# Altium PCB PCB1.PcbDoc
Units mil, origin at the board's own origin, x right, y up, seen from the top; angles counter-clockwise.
Board outline 2600 x 2600 mil, 4 copper layers (Top Layer, Layer 1, Layer 2, Bottom Layer), stack 68.756 mil thick; 22 components, 108 nets, 300 pads, 190 vias.
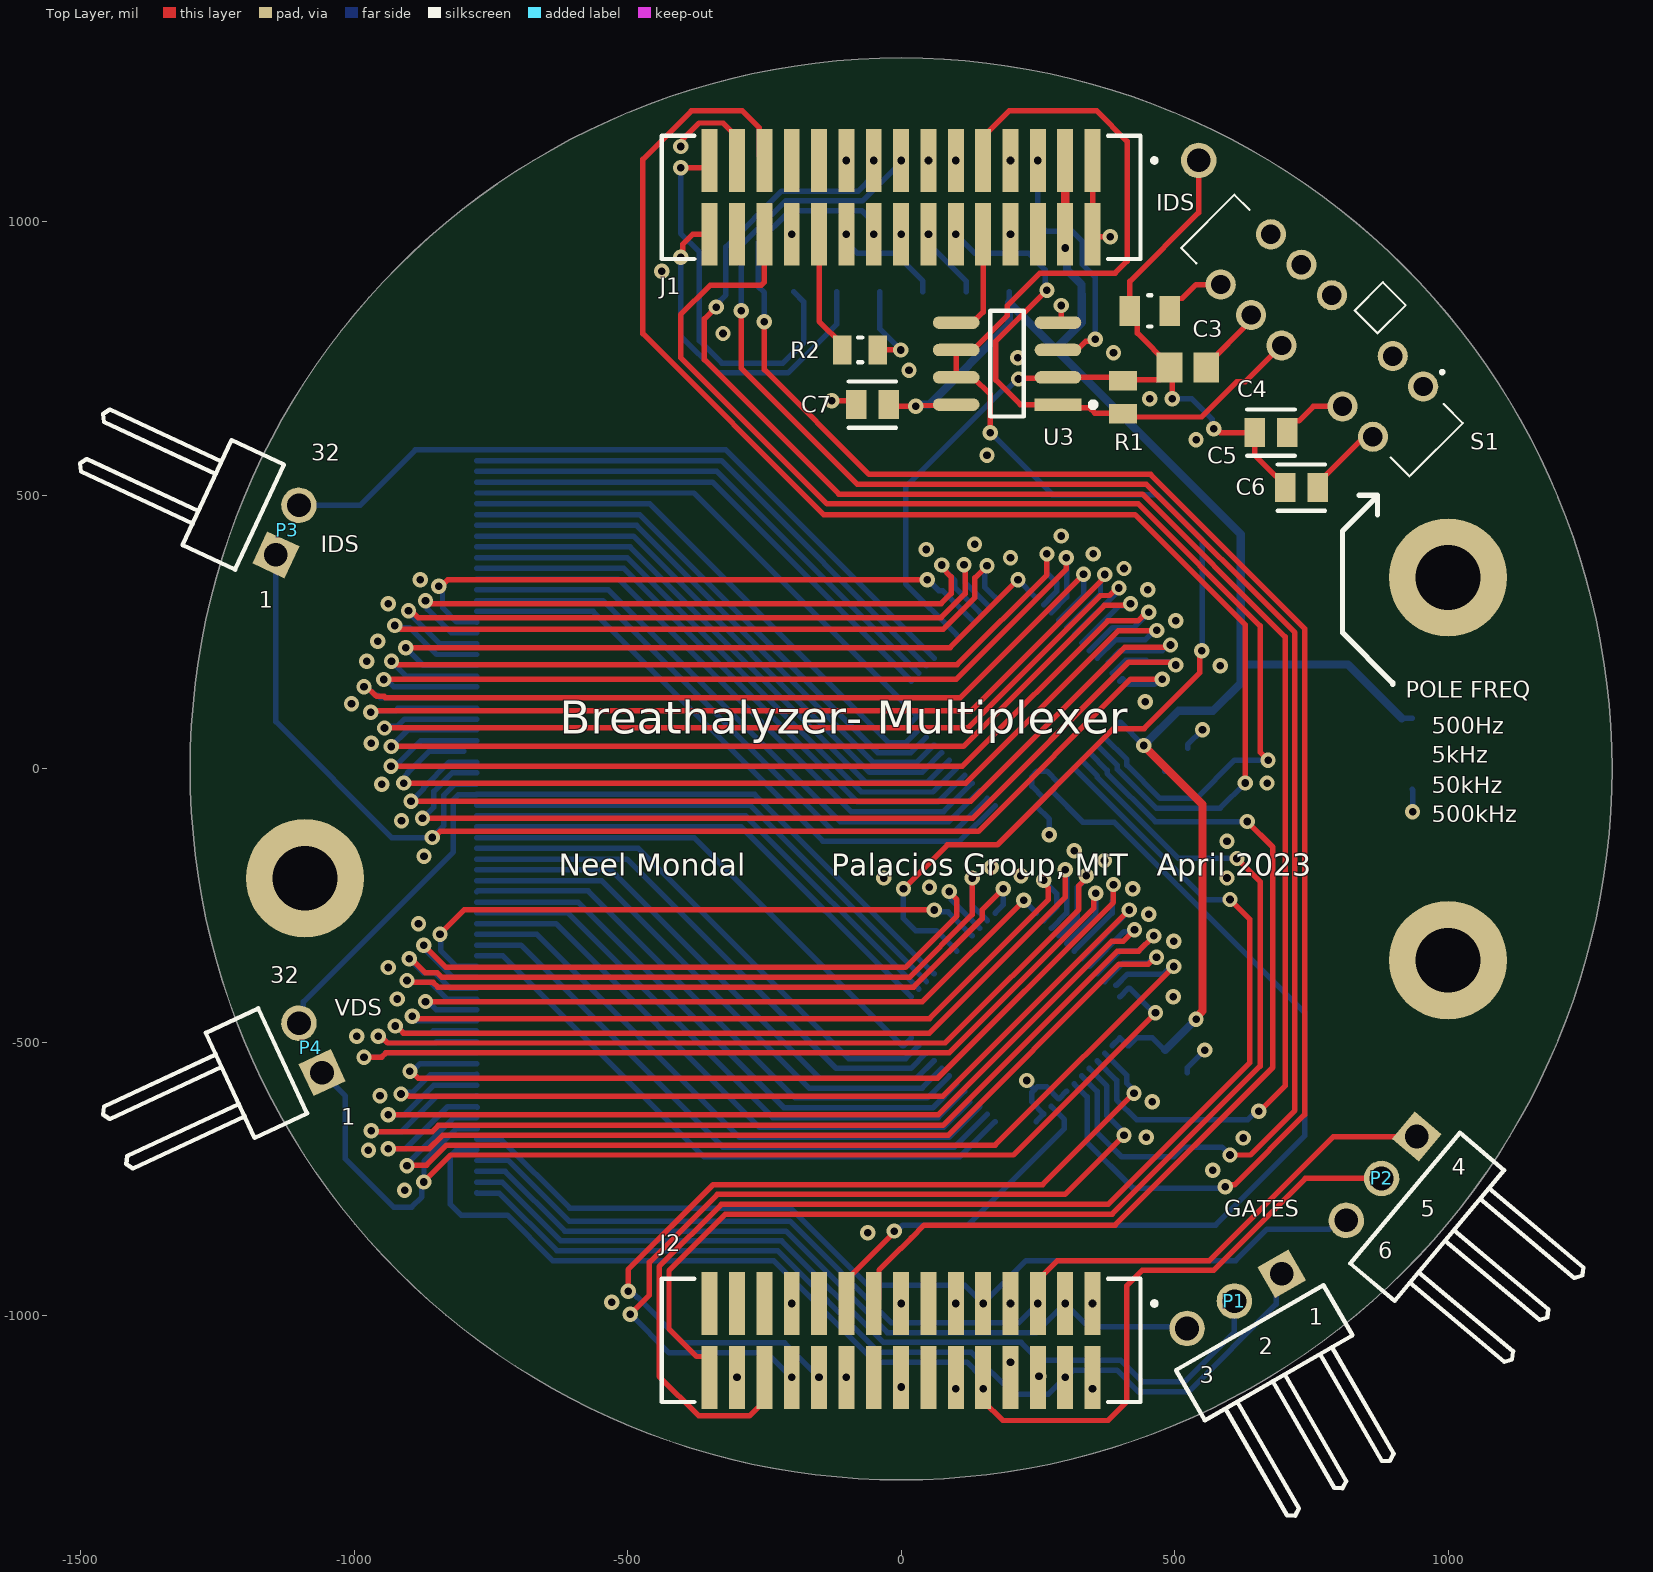
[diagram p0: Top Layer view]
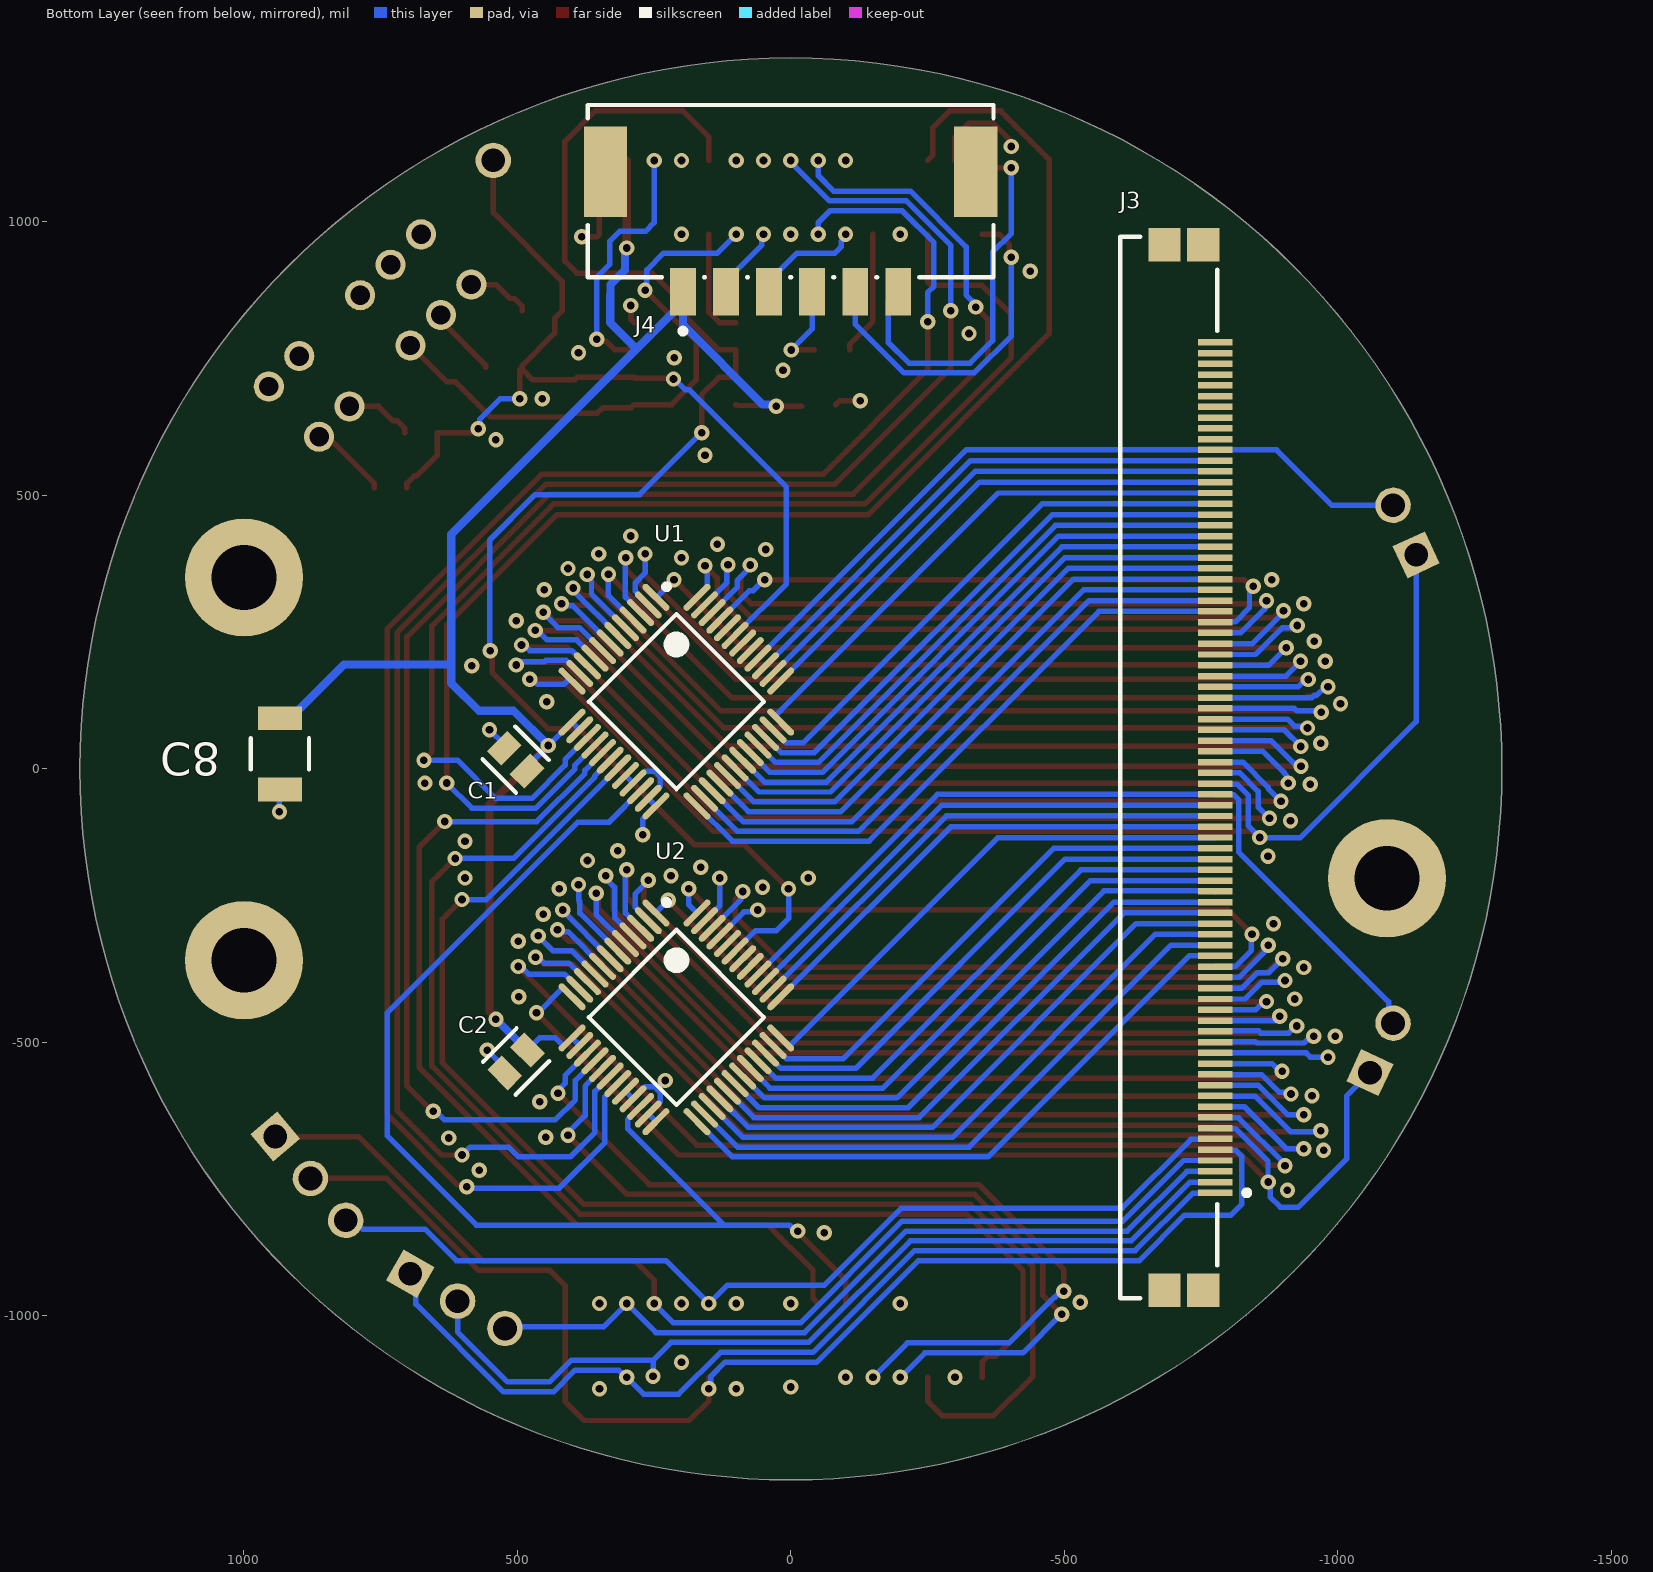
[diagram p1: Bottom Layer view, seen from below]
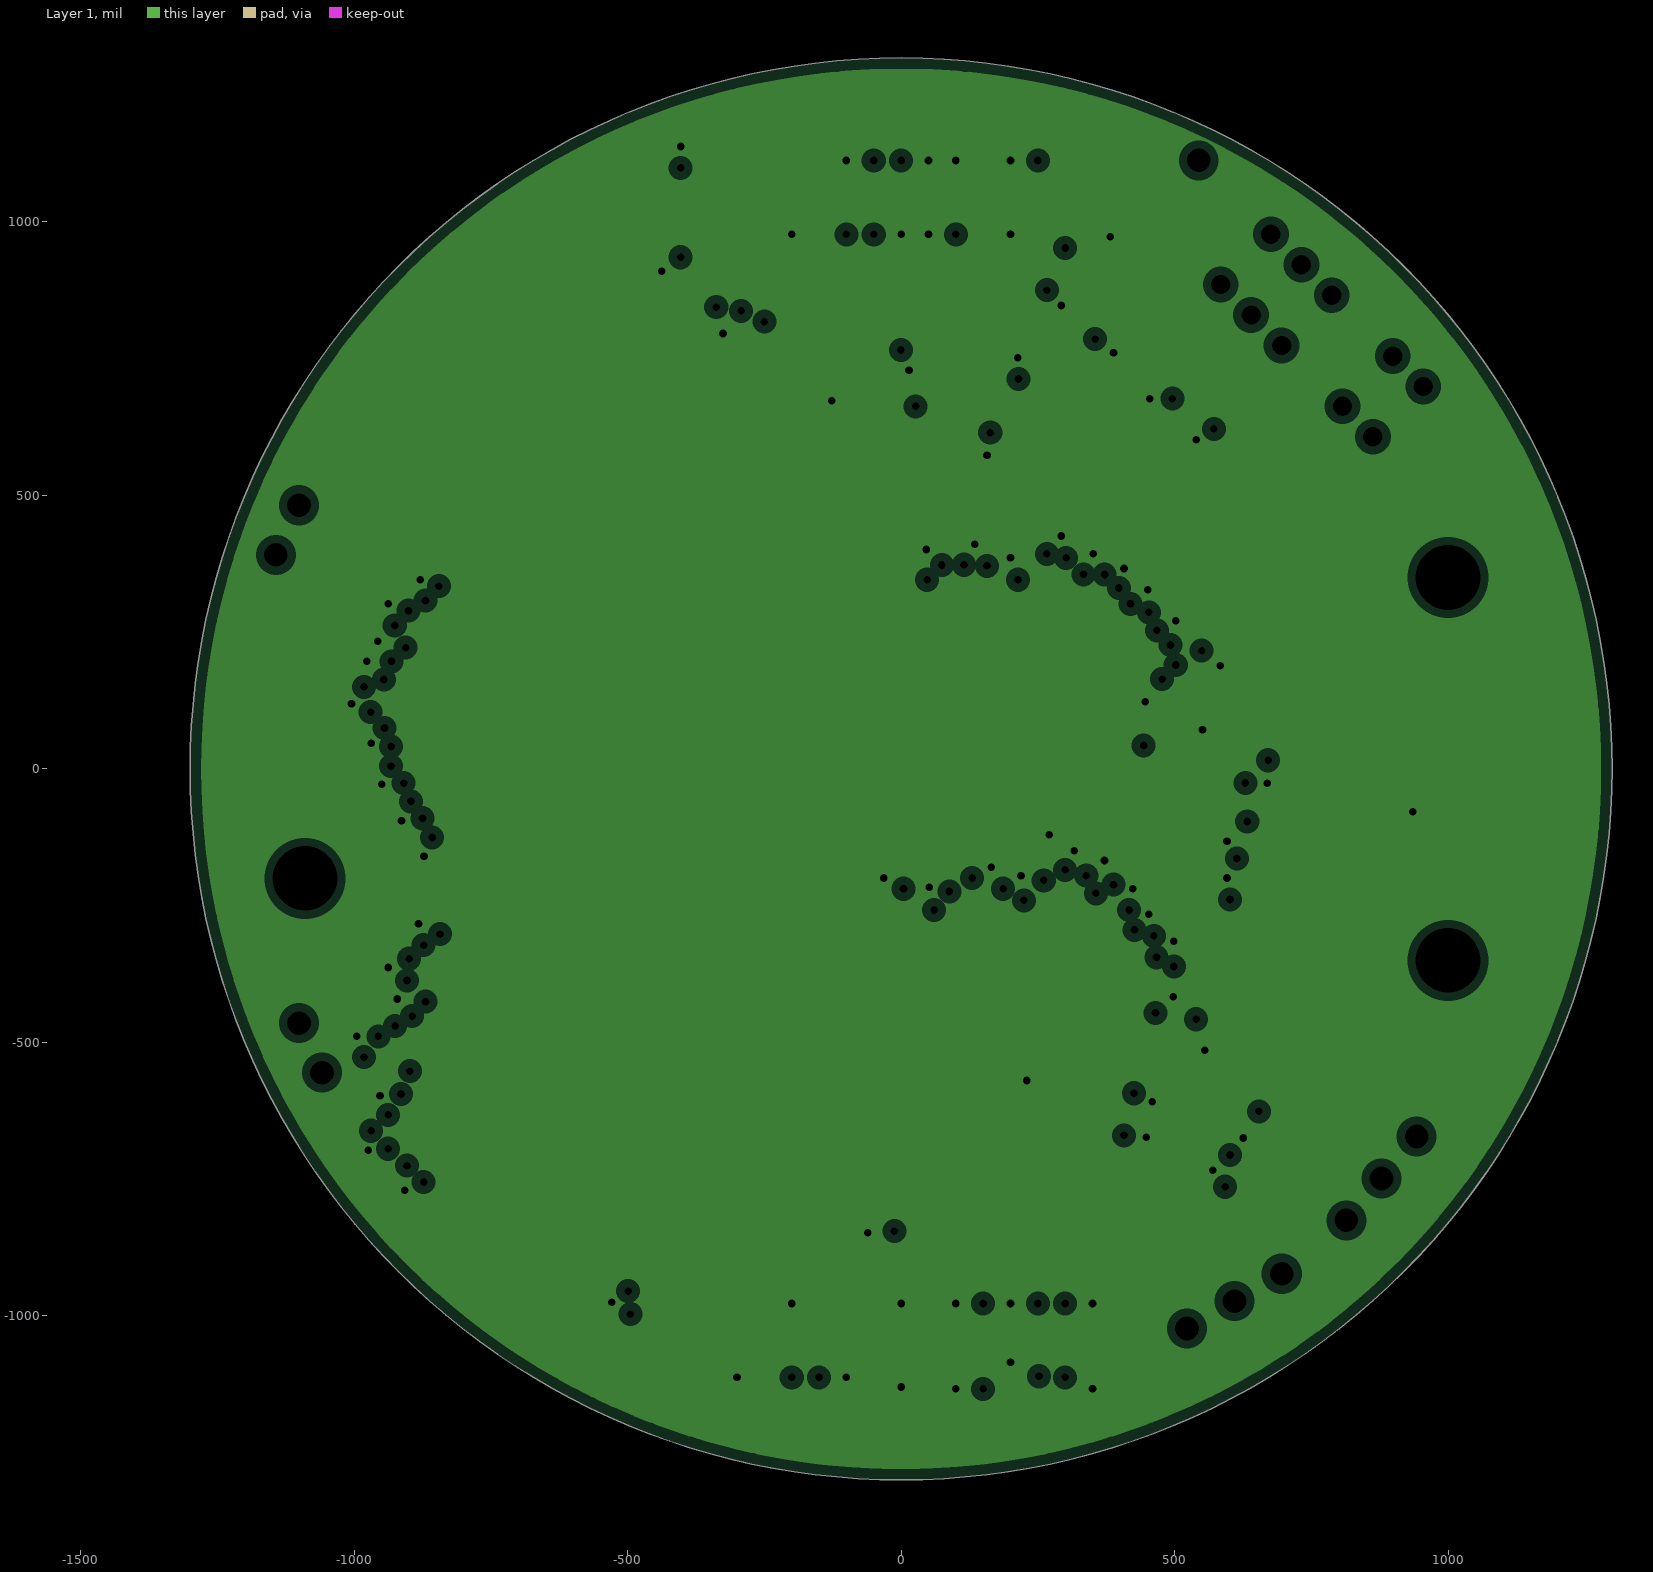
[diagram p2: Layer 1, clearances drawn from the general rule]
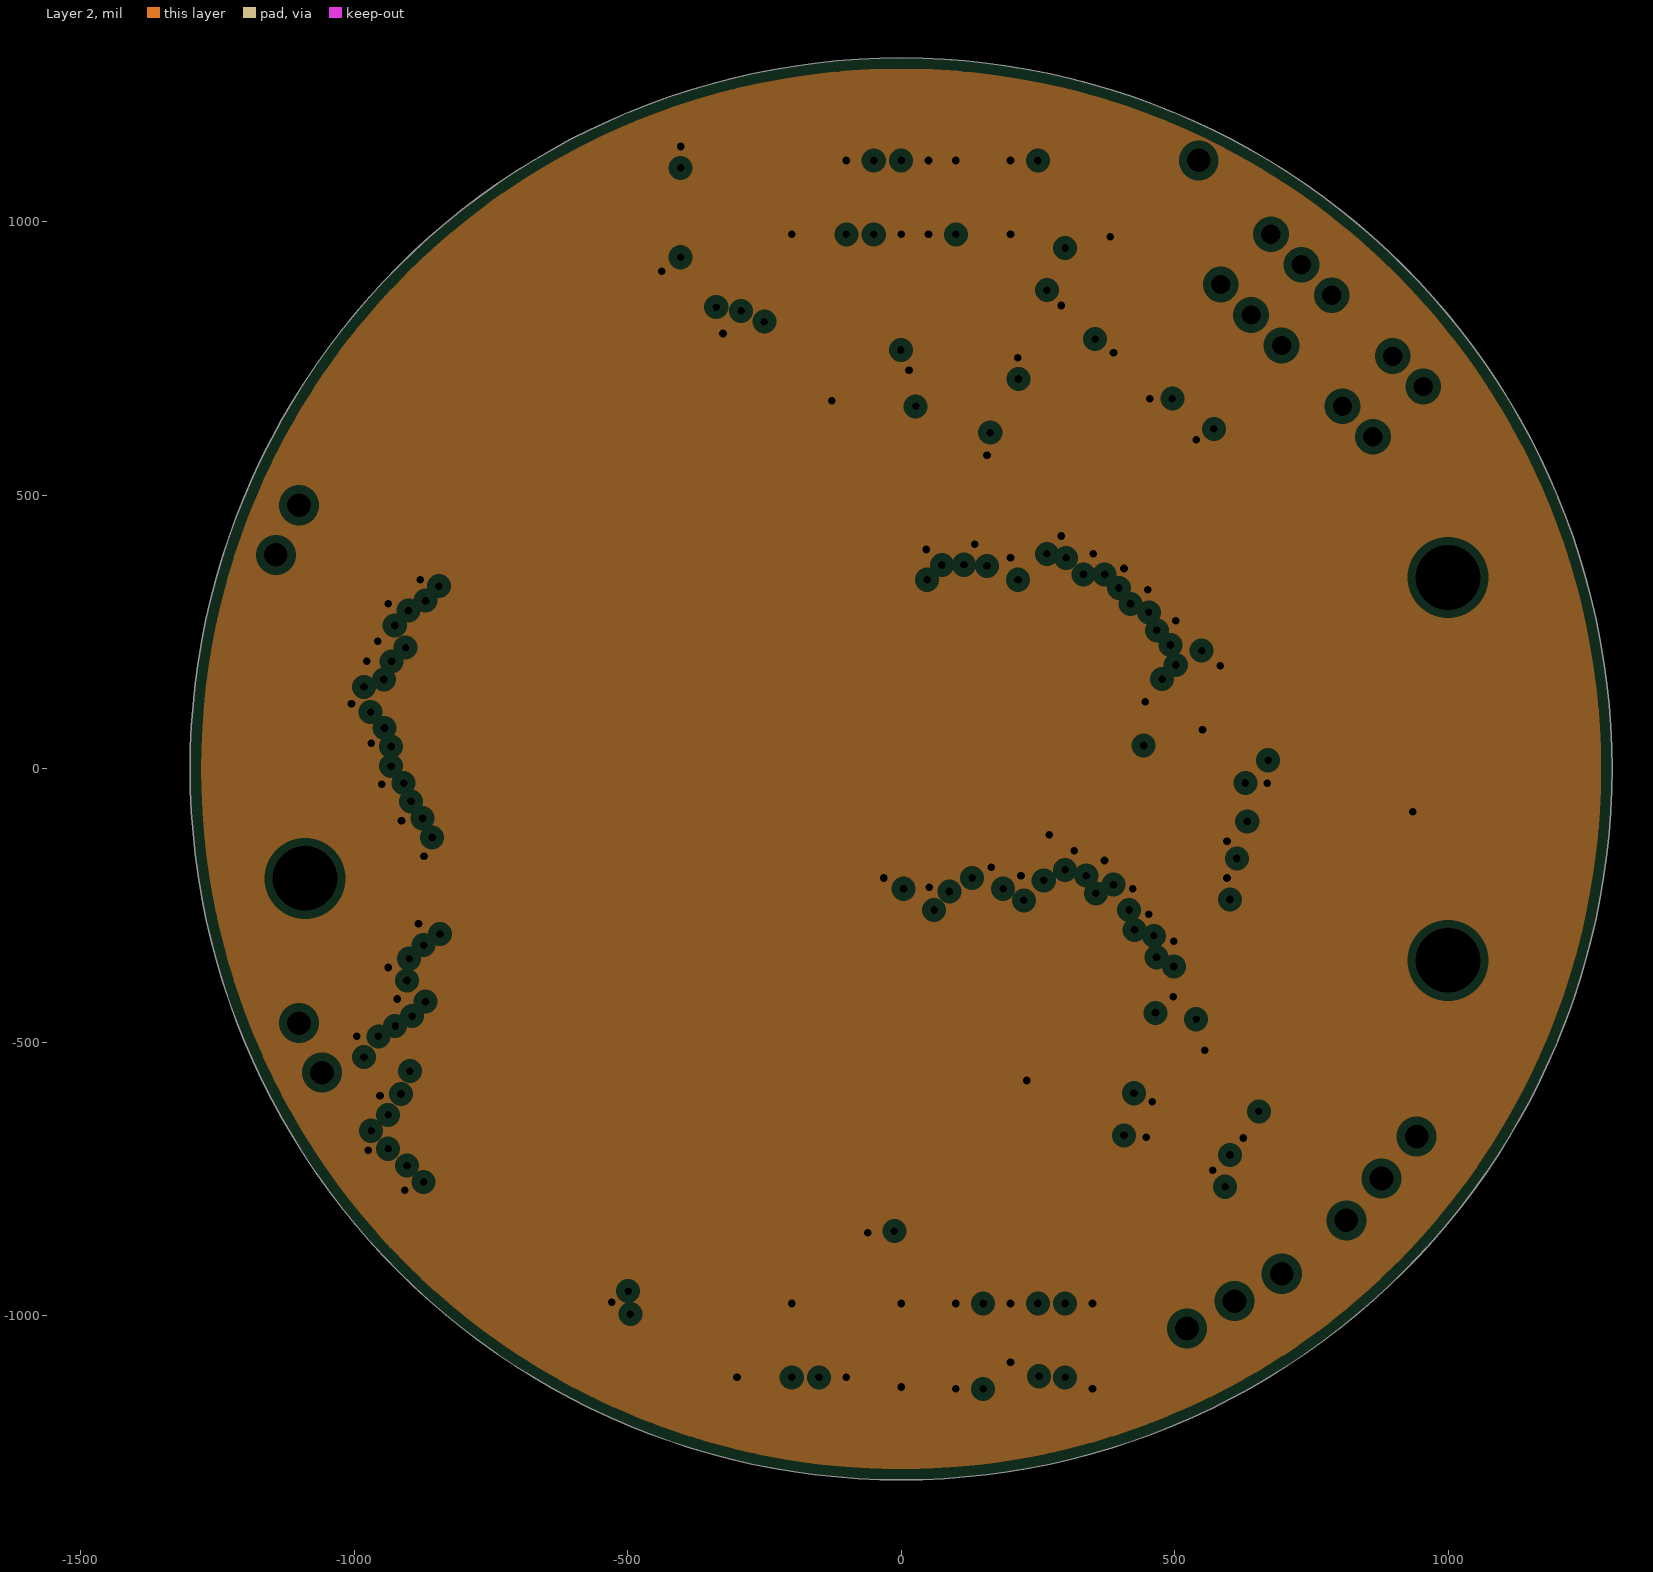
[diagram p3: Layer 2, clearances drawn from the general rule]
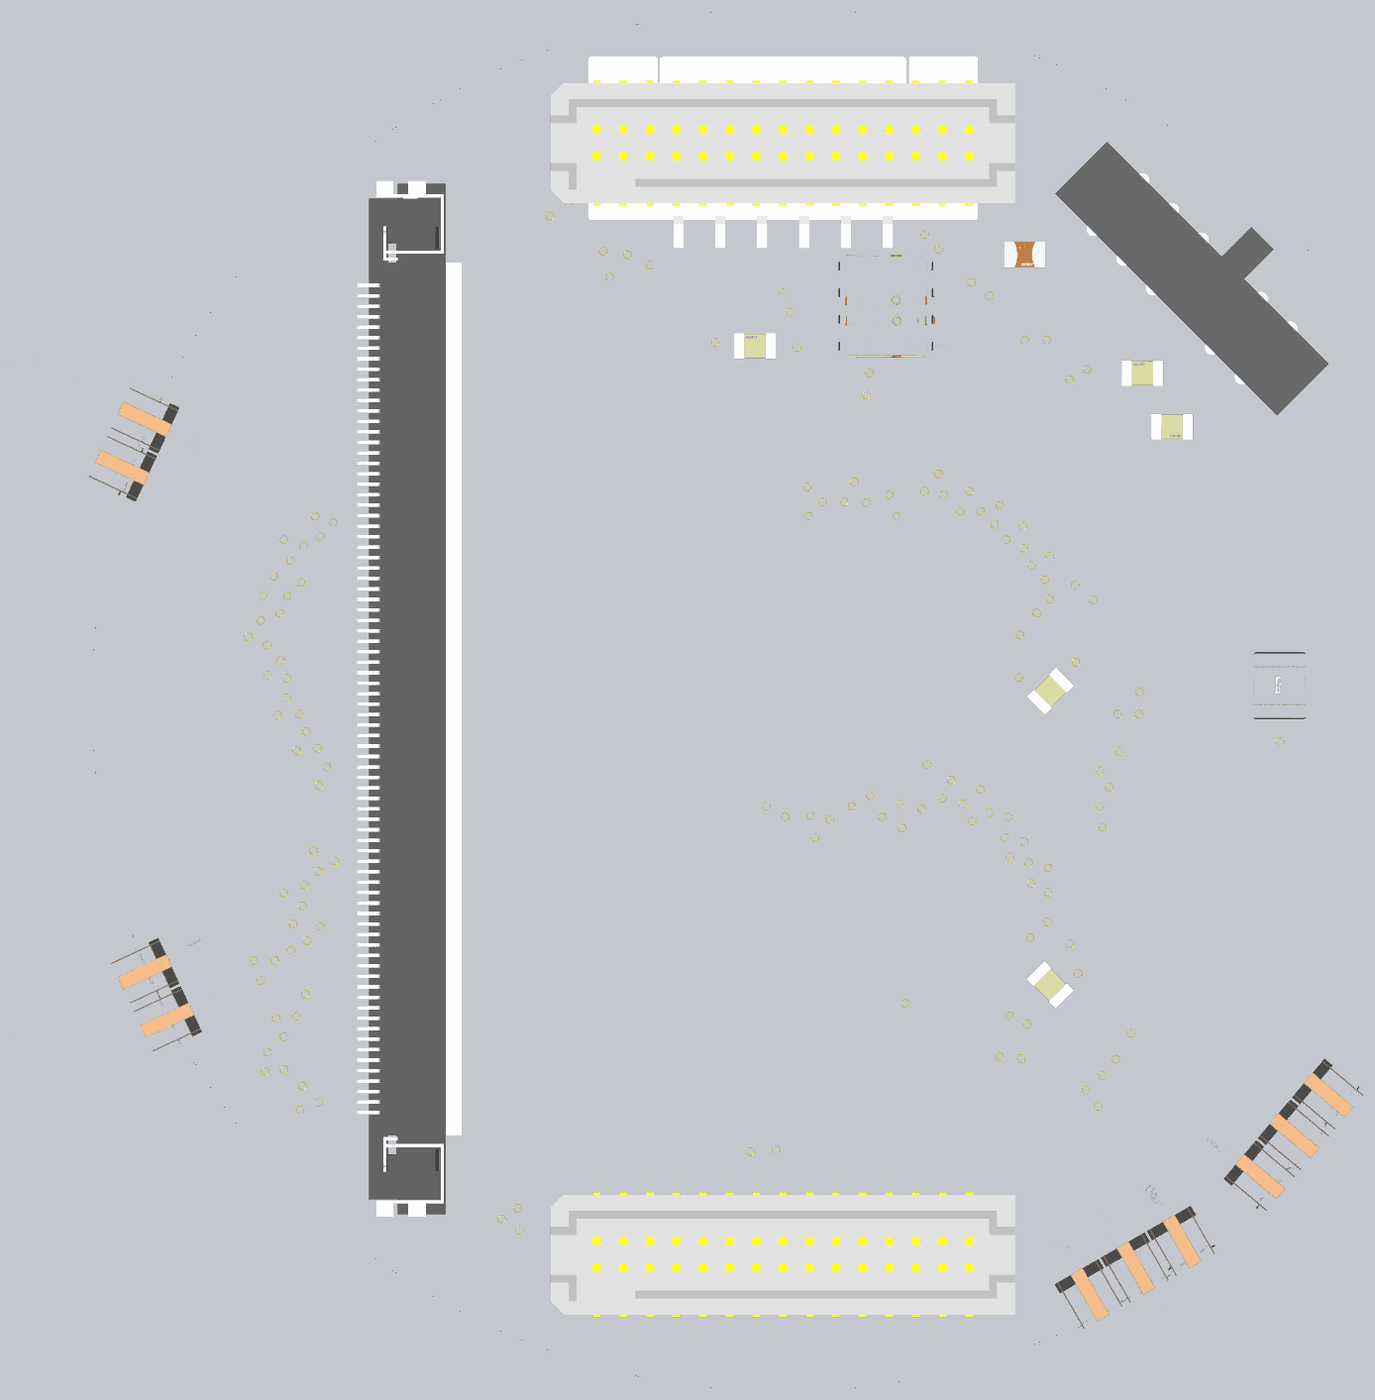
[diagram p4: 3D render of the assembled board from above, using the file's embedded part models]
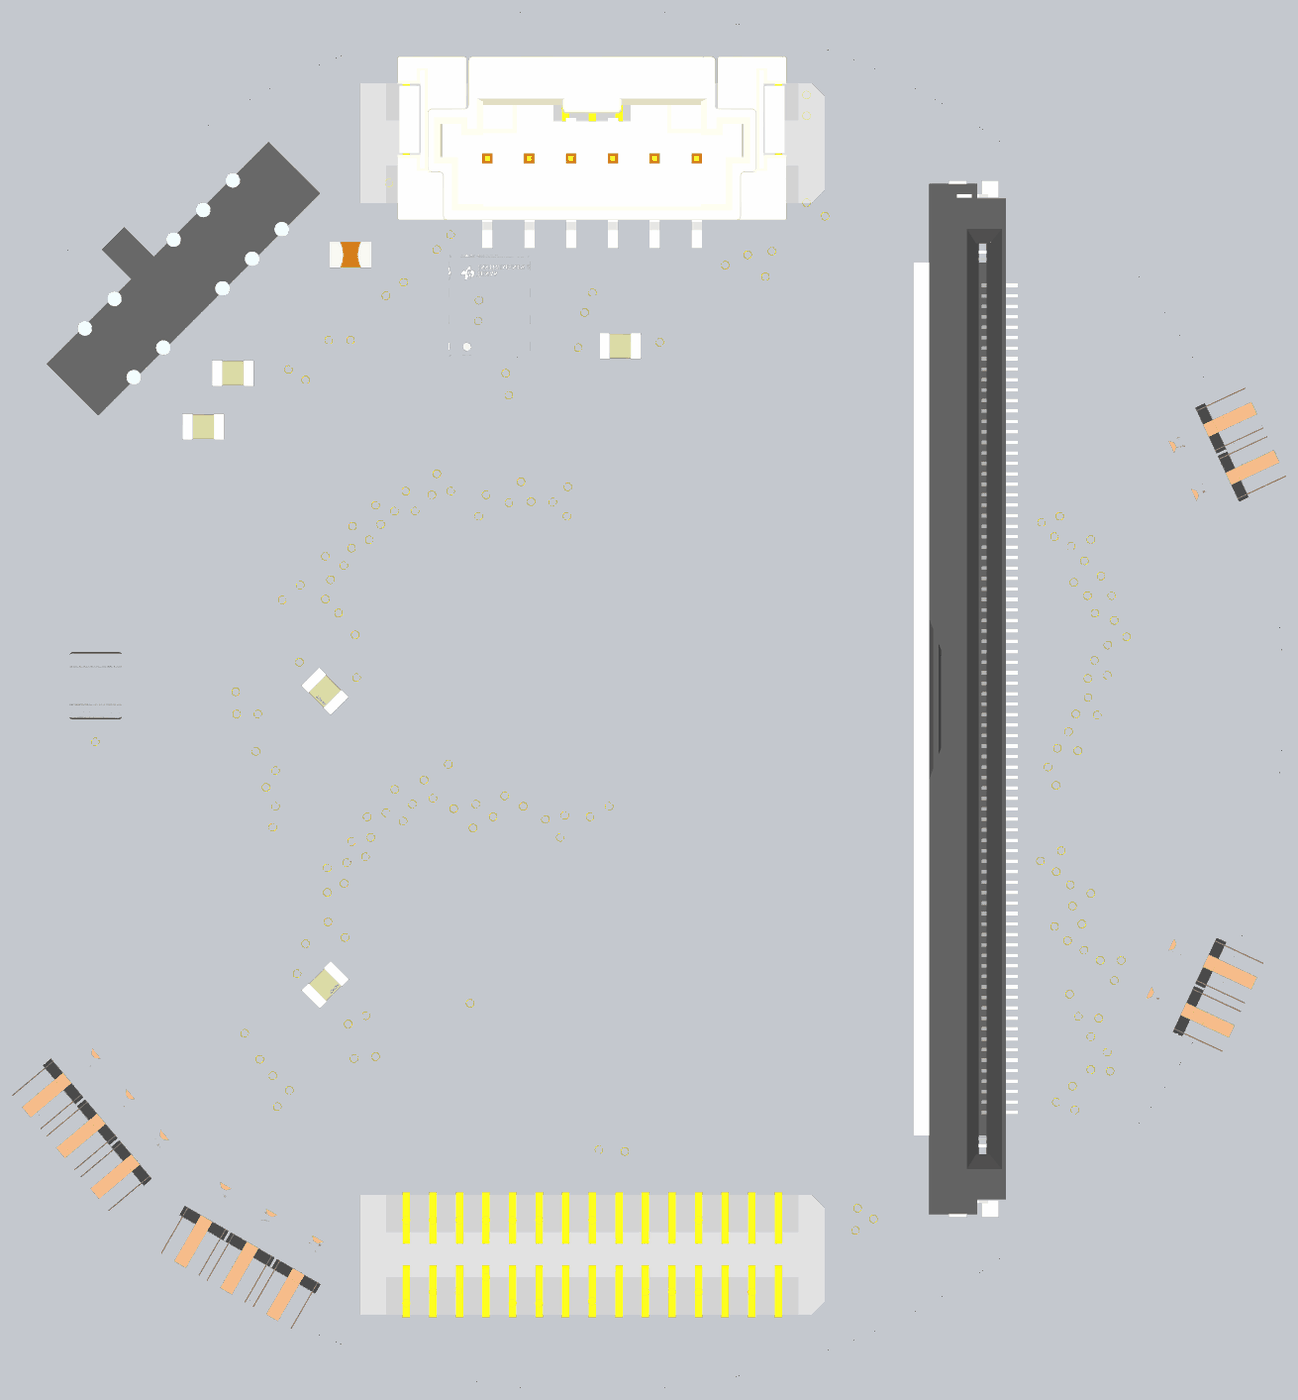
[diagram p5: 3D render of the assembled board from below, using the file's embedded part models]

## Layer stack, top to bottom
Top Solder: solder mask 0.5, Solder Resist, Dk 3.3
Top Layer: signal copper 0.7
Dielectric 1: prepreg 2.8, PP-006, Dk 4.1
Layer 1: plane copper 1.378, net GND
Dielectric1: core 59, FR-4, Dk 4.3
Layer 2: plane copper 1.378, net GND
Dielectric 2: prepreg 2.8, PP-006, Dk 4.1
Bottom Layer: signal copper 0.7
Bottom Solder: solder mask 0.5, Solder Resist, Dk 3.3

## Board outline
-1300,0 ccw(c0,0) 0,-1300 ccw(c0,0) 1300,0 ccw(c0,0) 0,1300 ccw(c0,0)

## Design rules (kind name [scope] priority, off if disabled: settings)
Clearance [All] p1: gap=8 ignorepadtopadclearanceinfootprint=FALSE except(6: Arc-SMDPad Track-SMDPad SMDPad-SMDPad; 12: Arc-Via Track-Via)
DiffPairsRouting [All] p1: maxlimit=10 minlimit=10 mostfreqgap=10 toplayer_minwidth=10 toplayer_maxwidth=10 toplayer_prefwidth=10 bottomlayer_minwidth=10 bottomlayer_maxwidth=10 bottomlayer_prefwidth=10 maxuncoupledlength=500
HoleSize [All] p1: absolutevalues=TRUE maxlimit=300 minlimit=14 maxpercent=80.000 minpercent=20.000
MinimumAnnularRing [All] p1: minimumring=7
MinimumSolderMaskSliver [All] p1: minsoldermaskwidth=0
PasteMaskExpansion [All] p1: expansion=10
PlaneClearance [All] p1: clearance=15
PlaneConnect [All] p1: pad.planeconnectstyle=Relief pad.reliefexpansion=20 pad.reliefentries=4 pad.reliefconductorwidth=10 pad.reliefairgap=10 via.planeconnectstyle=Direct via.reliefexpansion=20 via.reliefentries=4 via.reliefconductorwidth=10 via.reliefairgap=10
PolygonConnect [All] p1: thpad.connectstyle=Relief thpad.reliefconductorwidth=10 thpad.reliefentries=4 thpad.polygonreliefangle="90 Angle" thpad.airgapwidth=10 smdpad.connectstyle=Relief smdpad.reliefconductorwidth=10 smdpad.reliefentries=4 smdpad.polygonreliefangle="90 Angle" smdpad.airgapwidth=10 via.connectstyle=Direct via.reliefconductorwidth=10 via.reliefentries=4 via.polygonreliefangle="90 Angle" via.airgapwidth=10
RoutingVias [All] p1: holewidth=14 width=28 viastyle="Through Hole" minholewidth=14 minwidth=28 maxholewidth=14 maxwidth=28
SMDNeckDown [All] p1: percent=100.000
SilkToSolderMaskClearance SilkscreenOverComponentPads [IsPad] p1: minsilkscreentomaskgap=6 clearancetoexposedcopper=TRUE
SolderMaskExpansion [All] p1: expansion=10 istentingtop=FALSE
Width [All] p1: maxlimit=15 minlimit=8 preferedwidth=8
23 further rules are at their usual default settings.

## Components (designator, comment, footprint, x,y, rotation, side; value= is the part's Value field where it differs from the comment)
C1 "100 nF" FP-C0805C-DN-MFG 503.17,16.93 r45 bottom value="0.10 μF"
C2 "100 nF" FP-C0805C-DN-MFG 502.48,-535.01 r315 bottom value="0.10 μF"
C3 "330nF" FP-CC0805-0_85-MFG 454.89,837.55 r0 top value="330 nF"
C4 "33nF" CAPC2013X95X45NL10T25 524.49,734 r0 top
C5 "3.3nF" FP-C0805C-DN-MFG 676.21,614.89 r0 top value="3,300 pF"
C6 "330pF" FP-C0805C-DN-MFG 731.89,514.2 r180 top value="330 pF"
C7 "100 nF" FP-C0805C-DN-MFG -52.48,666 r0 top value="0.10 μF"
C8 "22uF" FP-GRM32-MFG 934.27,27.37 r270 bottom
J1 "TFM-115-02-L-D" SAMTEC_TFM-115-02-L-D 0,1045 r180 top locked
J2 "TFM-115-02-L-D" SAMTEC_TFM-115-02-L-D 0,-1045 r180 top locked
J3 "200485-0580" FP-200485-0580-MFG -690.96,2.49 r270 bottom locked
J4 "5600200620" FP-5600200620-MFG 0.58,1056.57 r0 bottom locked
P1 "DNP" 61300311021 663.97,-1067.6 r30 top locked
P2 "DNP" 61300311021 962,-819 r50 top locked
P3 "DNP" 61300211021 -1220.97,482.77 r245 top locked
P4 "DNP" 61300211021 -1178.71,-556.24 r295 top locked
R1 "1k" RESC2013X55X40LL15T20 405.85,679.55 r270 top
R2 "100" RESC2013X50X30LL20T20 -75.02,766 r180 top
S1 "SSSS212400" SSSS212400 954.6,699.09 r135 top locked
U1 "ADG732BSUZ-REEL" ADI-SU-48_N 209.3,123.04 r225 bottom
U2 "ADG732BSUZ-REEL" ADI-SU-48_N 209.3,-454.31 r225 bottom
U3 "OPA2388IDR" FP-D0008A-IPC_B 193.71,741 r180 top

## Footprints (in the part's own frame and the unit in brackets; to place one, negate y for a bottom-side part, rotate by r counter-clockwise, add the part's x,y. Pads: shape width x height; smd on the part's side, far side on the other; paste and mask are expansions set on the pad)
61300211021 [mm] "Pin Header, pitch 2.54 mm, THT, Angled, single row, 2p"
  rect 1.65x1.65 hole 1.1: 1(1.27,2.77)
  round 1.65 hole 1.1: 2(-1.27,2.77)
  silkscreen extent -2.69,-7.27 2.69,1.35, body extent -2.54,-7.27 2.54,3.09, height 2.58
61300311021 [mm] "Pin Header, pitch 2.54 mm, THT, Angled, single row, 3p"
  rect 1.65x1.65 hole 1.1: 1(2.54,2.77)
  round 1.65 hole 1.1: 2(0,2.77) 3(-2.54,2.77)
  silkscreen extent -3.96,-7.27 3.96,1.34, body extent -3.81,-7.27 3.81,3.09, height 2.58
ADI-SU-48_N [mm] "QFP, 48-Leads, Body 7x7mm, Pitch 0.5mm, IPC Medium Density"
  oval 1.65x0.3 smd: 1(-4.1,2.75) 2(-4.1,2.25) 3(-4.1,1.75) 4(-4.1,1.25) 5(-4.1,0.75) 6(-4.1,0.25) 7(-4.1,-0.25) 8(-4.1,-0.75) 9(-4.1,-1.25) 10(-4.1,-1.75) 11(-4.1,-2.25) 12(-4.1,-2.75) 25(4.1,-2.75) 26(4.1,-2.25) 27(4.1,-1.75) 28(4.1,-1.25) 29(4.1,-0.75) 30(4.1,-0.25) 31(4.1,0.25) 32(4.1,0.75) 33(4.1,1.25) 34(4.1,1.75) 35(4.1,2.25) 36(4.1,2.75)
  oval 0.3x1.65 smd: 13(-2.75,-4.1) 14(-2.25,-4.1) 15(-1.75,-4.1) 16(-1.25,-4.1) 17(-0.75,-4.1) 18(-0.25,-4.1) 19(0.25,-4.1) 20(0.75,-4.1) 21(1.25,-4.1) 22(1.75,-4.1) 23(2.25,-4.1) 24(2.75,-4.1) 37(2.75,4.1) 38(2.25,4.1) 39(1.75,4.1) 40(1.25,4.1) 41(0.75,4.1) 42(0.25,4.1) 43(-0.25,4.1) 44(-0.75,4.1) 45(-1.25,4.1) 46(-1.75,4.1) 47(-2.25,4.1) 48(-2.75,4.1)
  silkscreen extent -4.22,-2.88 2.88,3.57, body extent -3.5,-3.5 3.5,3.5, height 1.2
CAPC2013X95X45NL10T25 [mm] "Chip Capacitor, 2-Leads, Body 2.00x1.25mm, IPC Medium Density"
  rect 1.2x1.4 smd: 1(-0.85,0) 2(0.85,0)
  body extent -1.05,-0.67 1.05,0.67, height 0.95
FP-200485-0580-MFG [mm]
  rect 0.3x1.6 smd paste-1000 mask+0: 1(19.75,2.16) 2(19.25,2.16) 3(18.75,2.16) 4(18.25,2.16) 5(17.75,2.16) 6(17.25,2.16) 7(16.75,2.16) 8(16.25,2.16) 9(15.75,2.16) 10(15.25,2.16) 11(14.75,2.16) 12(14.25,2.16) 13(13.75,2.16) 14(13.25,2.16) 15(12.75,2.16) 16(12.25,2.16) 17(11.75,2.16) 18(11.25,2.16) 19(10.75,2.16) 20(10.25,2.16) 21(9.75,2.16) 22(9.25,2.16) 23(8.75,2.16) 24(8.25,2.16) 25(7.75,2.16) 26(7.25,2.16) 27(6.75,2.16) 28(6.25,2.16) 29(5.75,2.16) 30(5.25,2.16) 31(4.75,2.16) 32(4.25,2.16) 33(3.75,2.16) 34(3.25,2.16) 35(2.75,2.16) 36(2.25,2.16) 37(1.75,2.16) 38(1.25,2.16) 39(0.75,2.16) 40(0.25,2.16) 41(-0.25,2.16) 42(-0.75,2.16) 43(-1.25,2.16) 44(-1.75,2.16) 45(-2.25,2.16) 46(-2.75,2.16) 47(-3.25,2.16) 48(-3.75,2.16) 49(-4.25,2.16) 50(-4.75,2.16) 51(-5.25,2.16) 52(-5.75,2.16) 53(-6.25,2.16) 54(-6.75,2.16) 55(-7.25,2.16) 56(-7.75,2.16) 57(-8.25,2.16) 58(-8.75,2.16) 59(-9.25,2.16) 60(-9.75,2.16) 61(-10.25,2.16) 62(-10.75,2.16) 63(-11.25,2.16) 64(-11.75,2.16) 65(-12.25,2.16) 66(-12.75,2.16) 67(-13.25,2.16) 68(-13.75,2.16) 69(-14.25,2.16) 70(-14.75,2.16) 71(-15.25,2.16) 72(-15.75,2.16) 73(-16.25,2.16) 74(-16.75,2.16) 75(-17.25,2.16) 76(-17.75,2.16) 77(-18.25,2.16) 78(-18.75,2.16) 79(-19.25,2.16) 80(-19.75,2.16)
  rect 1.55x1.5 smd paste+0 mask+0: 81(-24.275,1.6) 82(24.275,1.6) 83(-24.275,-0.2) 84(24.275,-0.2)
  silkscreen extent -24.65,-2.26 24.65,3.74, body extent -24.74,-2.21 24.75,2.79, height 5.7
FP-5600200620-MFG [mm]
  rect 1.2x2.2 smd paste+0 mask+0: 1(5,4.68) 2(3,4.68) 3(1,4.68) 4(-1,4.68) 5(-3,4.68) 6(-5,4.68)
  rect 2x4.2 smd paste+0 mask+0: 7(-8.6,-0.9) 8(8.6,-0.9)
  silkscreen extent -9.43,-4 9.43,6.63, body extent -9.3,-3.9 9.3,5.25, height 8.2
FP-C0805C-DN-MFG [mm]
  rect 0.95x1.35 smd paste+0 mask+0: 1(-0.75,0) 2(0.75,0)
  silkscreen extent -1.1,-1.07 1.1,1.08, body extent -1,-0.62 1,0.63, height 0.88
FP-CC0805-0_85-MFG [mm]
  rect 0.95x1.4 smd paste+0 mask+0: 1(-0.925,0) 2(0.925,0)
  silkscreen extent -0.08,-0.72 0.08,0.72, body extent -1.6,-1.05 1.6,1.05, height 0.25
FP-D0008A-IPC_B [mil]
  rect 85.4x22.92 smd paste+0 mask+0: 1(-93.06,75)
  rrect100% 85.4x22.92 smd paste+0 mask+0: 2(-93.06,25) 3(-93.06,-25) 4(-93.06,-75) 5(93.06,-75) 6(93.06,-25) 7(93.06,25) 8(93.06,75)
  silkscreen extent -162,-97 31,97, body extent -146,-106 146,106, height 10
FP-GRM32-MFG [mm]
  rect 1.1x2.05 smd paste+0 mask+0: 1(-1.65,0) 2(1.65,0)
  silkscreen extent -0.72,-1.35 0.72,1.35, body extent -1.6,-1.25 1.6,1.25, height 2.7
RESC2013X50X30LL20T20 [mm] "Chip Resistor, 2-Leads, Body 2.00x1.25mm, IPC High Density"
  rect 0.85x1.35 smd: 1(-0.825,0) 2(0.825,0)
  silkscreen extent -0.1,-0.58 0.1,0.58, body extent -1.1,-0.73 1.1,0.73, height 0.5
RESC2013X55X40LL15T20 [mm] "Chip Resistor, 2-Leads, Body 2.00x1.25mm, IPC High Density"
  rect 0.9x1.3 smd: 1(-0.775,0) 2(0.775,0)
  body extent -1.07,-0.7 1.07,0.7, height 0.55
SAMTEC_TFM-115-02-L-D [mm]
  rect 0.74x2.92 smd: 01(-8.89,-1.715) 02(-8.89,1.715) 03(-7.62,-1.715) 04(-7.62,1.715) 05(-6.35,-1.715) 06(-6.35,1.715) 07(-5.08,-1.715) 08(-5.08,1.715) 09(-3.81,-1.715) 10(-3.81,1.715) 11(-2.54,-1.715) 12(-2.54,1.715) 13(-1.27,-1.715) 14(-1.27,1.715) 15(0,-1.715) 16(0,1.715) 17(1.27,-1.715) 18(1.27,1.715) 19(2.54,-1.715) 20(2.54,1.715) 21(3.81,-1.715) 22(3.81,1.715) 23(5.08,-1.715) 24(5.08,1.715) 25(6.35,-1.715) 26(6.35,1.715) 27(7.62,-1.715) 28(7.62,1.715) 29(8.89,-1.715) 30(8.89,1.715)
  silkscreen extent -11.87,-2.86 11.11,2.86, body extent -11.11,-3.05 11.11,2.92, height 5.71
SSSS212400 [mm]
  round 1.4 hole 0.9: 1(0,0) 2(2,0) 3(6,0) 4(8,0) 5(10,0) 6(0,3.3) 7(2,3.3) 8(6,3.3) 9(8,3.3) 10(10,3.3)
  silkscreen extent -2.5,-2.1 12.5,3.4, body extent -2.5,-2.1 12.5,3.65, height 3.6

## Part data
C1 C2 C7: library part CMP-2007-00279-2, "CAP CER 0.1UF 50V X7R 0805", Capacitance="0.10 μF", Manufacturer=KEMET, Manufacturer Part Number=C0805C104K5RACTU, Package=C0805C-DN, Temperature="-55°C to +125°C", Temperature Characteristic=X7R, Temperature Coefficient=30ppm/°C, Temperature Range High=+125°C, Temperature Range Low=-55°C, Tolerance=0.1, Voltage Rating="50 V"
C3: library part CMP-03422-000882-1, "Surface Mount Ceramic Multilayer Capacitor 0.33uF 10% X7R 16V 0805 Blister T/R", Capacitance="330 nF", Manufacturer=Yageo, Manufacturer Part Number=CC0805KKX7R7BB334, Package=CC0805-0.85, Temperature="-30°C to +85°C", Temperature Characteristic=X7R, Temperature Range High=+85°C, Temperature Range Low=-30°C, Tolerance=0.1, Voltage Rating="16 V"
C4: library part CMP-1036-04169-2, Manufacturer=Murata, Part Number=GRM219R71H333KA01D
C5: library part CMP-2007-00373-2, "CAP CER 3300PF 50V X7R 0805", Capacitance="3,300 pF", Manufacturer=KEMET, Manufacturer Part Number=C0805C332K5RACTU, Package=C0805C-DN, Temperature="-55°C to +125°C", Temperature Characteristic=X7R, Temperature Coefficient=30ppm/°C, Temperature Range High=+125°C, Temperature Range Low=-55°C, Tolerance=0.1, Voltage Rating="50 V"
C6: library part CMP-2007-00598-2, "CAP CER 330PF 50V C0G/NP0 0805", Capacitance="330 pF", Manufacturer=KEMET, Manufacturer Part Number=C0805C331J5GACTU, Package=C0805C-DN, Temperature="-55°C to +125°C", Temperature Characteristic=C0G, Temperature Coefficient=30ppm/°C, Temperature Range High=+125°C, Temperature Range Low=-55°C, Tolerance=0.05, Voltage Rating="50 V"
C8: library part CMP-2000-05458-2, "CAP CER 22UF 25V X5R 1210", Manufacturer="Murata Electronics North America", Manufacturer Part Number=GRM32ER61E226KE15L, Operating Temperature="-55°C ~ 85°C", Package=GRM32, Package / Case="1210 (3225 Metric)", Standard Package=1,000, Temperature="-55°C to +85°C", Temperature Characteristic=X5R, Temperature Range High=+85°C, Temperature Range Low=-55°C, Tolerance=10%, Voltage - Rated=25V
J1 J2: Package=None
J3: library part CMP-04775-000018-1, "0.5 ONE-TOUCH ST 80P"
J4: library part CMP-04776-000066-1, "CONN HEADER SMD 6POS 2MM", Current Rating=3A, Manufacturer=Molex, Temperature="-40°C to +125°C", Temperature Range High=+125°C, Temperature Range Low=-40°C, Voltage Rating=125V
P1 P2: library part CMP-1502-01061-1, "THT Angled Pin Header WR-PHD, Pitch 2.54 mm, Single Row, 3 pins", Contact Resistance=20mOhm, Manufacturer="Wurth Elektronik", Operating Temperature=-40to105degC, Package Reference=61300311021, Rated Current=3A, Withstanding Voltage=500VAC, Working Voltage=250VAC
P3 P4: library part CMP-1502-01059-1, "THT Angled Pin Header WR-PHD, Pitch 2.54 mm, Single Row, 2 pins", Contact Resistance=20mOhm, Manufacturer="Wurth Elektronik", Operating Temperature=-40to105degC, Package Reference=61300211021, Rated Current=3A, Withstanding Voltage=500VAC, Working Voltage=250VAC
R1: library part CMP-2001-04738-1, "TNPW08051K00BEEN", Manufacturer="Vishay Dale"
R2: library part CMP-2001-04901-1, Manufacturer="Vishay Dale", Part Number=CRCW0805100RFKEA
S1: "Switch", Manufacturer_Name="ALPS Electric", Mouser Part Number=688-SSSS212400
U1 U2: library part CMP-0798-00236-1, "1.8 to 5.5 V / +/-2.5 V, 4 Ohm, 32-Channel Analog Multiplexer, -40 to 85 degC, 48-pin QFP (SU-48), Reel", Manufacturer="Analog Devices"
U3: library part CMP-04895-000483-1, "IC OPAMP ZER-DRIFT 2CIRC 8SOIC", Max Operating Temperature=125°C, Min Operating Temperature=-40°C

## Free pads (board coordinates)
  round 65 hole 43: 3(544.17,1112.52)
  round 216.54 hole 118.11: 4(-1090,-200) 4(1000,-350) 4(1000,350)

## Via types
v1: diameter 28, hole 14, Top Layer to Bottom Layer, tented both sides, 189 vias
v2: diameter 28, hole 14, Top Layer to Bottom Layer, 1 vias

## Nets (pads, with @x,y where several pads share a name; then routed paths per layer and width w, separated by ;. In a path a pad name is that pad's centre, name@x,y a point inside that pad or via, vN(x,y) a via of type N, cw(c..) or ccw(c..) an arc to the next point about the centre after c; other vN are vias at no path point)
1V_REF: J1.05 U3.3 | length 474.4
  Top Layer w10: U3.3 321.5,766 337.74,782.24 351.41,782.24 v1(354.86,785.68)
  Bottom Layer w10: v1(250,1112.52) 250,998.71 265.29,983.43 312.84,983.43 331,965.27 331,922.9 354.86,899.04 v1(354.86,785.68)
2V_REF: J1.06
3V3: C1.1 C2.1 C7.2 C8.1 J1.03 J1.04 J4.1 U1.13 U1.14 U2.13 U2.14 U3.8 | length 3138.8
  Top Layer w10: C7.2@-19.86,662.9 v1(26.53,662.9) 28.08,664.45 99.1,664.45 U3.8 ; v1(539.36,-457.79) v1@539.36,-454.58
  Top Layer w15: v1(300,952.43) J1.03 ; v1(443.58,42.73) 551.01,-64.69 551.01,-442.93 v1@539.36,-454.58
  Bottom Layer w10: v1(26.53,662.9) v1@29.97,666.35 ; J4.1@197.43,852.63 J4.1 ; v1(300,952.43) v1@303.44,948.98 ; 329.8,868.6 330.4,868 ; U2.14 U2.13 414.66,-506.56 415.84,-506.56 430.51,-491.89 459.36,-491.89 C2.1 C2.1@483.03,-514.13 ; U1.14 U1.13 400.85,85.46 v1(443.58,42.73) 482.29,4.02 C1.1 ; C8.1@915.56,92.33 C8.1
  Bottom Layer w15: v1@29.97,666.35 51.55,666.35 197.43,812.23 197.43,852.63 621.09,428.97 621.09,190.69 ; 282.15,767.91 330.4,816.17 330.4,868 ; v1@303.44,948.98 303.44,912.12 329.8,885.77 329.8,868.6 ; v1(443.58,42.73) 507.18,106.33 570.21,106.33 621.09,157.21 621.09,190.69 ; C2.1@483.03,-514.13 v1(539.36,-457.79) ; C8.1@915.56,92.33 817.21,190.69 621.09,190.69
5KHZ_POLE: C4.2 S1.9 | length 129.9
  Top Layer w10: C4.2 557.95,737.94 640.02,820.01 S1.9
50KHZ_POLE: C5.2 S1.7 | length 125.8
  Top Layer w10: C5.2 705.74,622.76 719.44,636.46 727.31,636.46 753.75,662.9 S1.7
500HZ_POLE: C3.2 S1.10 | length 118.1
  Top Layer w10: C3.2 491.31,846.41 505.01,860.11 513.87,860.11 539.36,885.61 S1.10
500KHZ_POLE: C6.1 S1.6 | length 144.5
  Top Layer w10: C6.1 761.42,522.08 837.93,598.59 854.1,598.59 S1.6
!ADC_CS: J1.21
!BME_CS: J1.29 J4.6 | length 714.4
  Top Layer w10: v1(-402.99,1099) -359.57,1099 -350,1108.57 J1.29
  Bottom Layer w10: v1(-402.99,1099) -402.99,979.34 -369,945.34 -369,783.27 -327.73,742 -216,742 -178,780 -178,854.05 J4.6
!CHIP_EN: J2.19 U1.22 U2.22 | length 2147.8
  Top Layer w10: J2.19 -100,-934.57 -12.4,-846.96 v1(-12.4,-845.1)
  Bottom Layer w10: v1(-12.4,-845.1) -7.99,-845.1 3.03,-834.08 122.13,-834.08 ; U2.22 274.72,-617.66 298.5,-641.43 298.5,-657.71 122.13,-834.08 ; U1.22 332.13,-97.22 389.7,-97.22 738.02,-445.54 738.02,-670.97 574.91,-834.08 122.13,-834.08
!DAC_CS: J1.23
!GATE_SHDN: J1.28
+11V: J2.13
-11V: J2.14
DRAIN_SEL0: J2.22 U2.15 | length 1607.8
  Top Layer w10: v1(-499,-955) -499,-915.62 -343.48,-760.1 258.93,-760.1 v1(425.97,-593.05)
  Bottom Layer w10: v1(-499,-955) -494.13,-955 -483.24,-965.89 -482.25,-965.89 -398.54,-1049.6 -212.92,-1049.6 v1(-150,-1112.52) ; U2.15 412.26,-559.83 412.26,-574.47 425.97,-588.18 v1(425.97,-593.05)
DRAIN_SEL1: J1.17 U2.16 | length 3102.1
  Top Layer w10: v1(-338,844.41) -359.57,822.85 -359.57,748.38 -113.62,502.43 441.2,502.43 702.02,241.61 702.02,-579.43 655.3,-626.16 v1(654.13,-626.16)
  Bottom Layer w10: v1(-338,844.41) -338,849.28 -320.45,866.83 -320.45,954.57 -218.46,1056.57 -78.06,1056.57 -50,1084.62 v1(-50,1112.52) ; U2.16 394.26,-569.67 394.26,-605.18 430.51,-641.43 633.98,-641.43 649.26,-626.16 v1(654.13,-626.16)
DRAIN_SEL2: J2.24 U2.17 | length 1564.8
  Top Layer w10: v1(-495.09,-996.89) -460.38,-962.18 -460.38,-902.45 -336.03,-778.1 299.59,-778.1 v1(407.69,-670)
  Bottom Layer w10: v1(-495.09,-996.89) -424.38,-1067.6 -244.92,-1067.6 v1(-200,-1112.52) ; U2.17 344.32,-548.06 376.26,-580 376.26,-633.79 407.69,-665.22 v1(407.69,-670)
DRAIN_SEL3: J1.15 U2.18 | length 3211.5
  Top Layer w10: v1(-292.34,837.55) -292.34,732.8 -79.98,520.43 448.65,520.43 720.02,249.06 720.02,-624.51 638.53,-706 v1(601.3,-706)
  Bottom Layer w10: v1(-292.34,837.55) -292.34,957.22 -211,1038.57 -70.6,1038.57 0,1109.17 v1(0,1112.52) ; U2.18 330.4,-561.98 358.26,-589.84 358.26,-664.41 403.44,-709.59 498.14,-709.59 516.14,-691.59 586.44,-691.59 600.85,-706 v1(601.3,-706)
DRAIN_SEL4: J1.18 U2.19 | length 3181.6
  Top Layer w10: v1(-250,817.87) -250,730.06 -58.37,538.43 456.11,538.43 738.02,256.52 738.02,-631.96 609.43,-760.56 596.04,-760.56 v1(592.59,-764)
  Bottom Layer w10: v1(-250,817.87) -250,870.82 -261.34,882.17 -261.34,962.77 -203.54,1020.57 -71.85,1020.57 -50,998.71 v1(-50,977.48) ; U2.19 316.48,-575.9 340.26,-599.68 340.26,-683.38 423.66,-766.78 589.81,-766.78 v1(592.59,-764)
GATE1: J2.04 J3.1 P1.1 | length 1783.1
  Bottom Layer w10: J3.1 -775.09,-775.98 -734.57,-775.98 -629.54,-881 -225.74,-881 -40,-1066.73 128.61,-1066.73 205.1,-1143.22 269.3,-1143.22 v1(300,-1112.52) 301.63,-1112.52 314.86,-1099.3 394.36,-1099.3 434.04,-1138.98 525.43,-1138.98 685.69,-978.72 685.69,-968.38 686.23,-967.84 686.23,-911.81 P1.1@685.69,-911.27
GATE2: J2.06 J3.2 P1.2 | length 1653.8
  Bottom Layer w10: J3.2 -775.8,-755.58 -729.5,-755.58 -622.09,-863 -218.28,-863 -32.55,-1048.73 219.34,-1048.73 252.04,-1081.43 ; v1(252.04,-1110.48) 252.04,-1081.43 ; P1.2@614.98,-981.98 609.44,-987.51 609.44,-1029.51 517.98,-1120.98 441.49,-1120.98 401.81,-1081.3 307.4,-1081.3 307.27,-1081.43 252.04,-1081.43
GATE3: J2.03 J3.3 P1.3 | length 1459.6
  Bottom Layer w10: J3.3 -723.93,-735.7 -614.63,-845 -210.83,-845 -25.09,-1030.73 246.75,-1030.73 v1(300,-977.48) 342.61,-1020.09 511.67,-1020.09 P1.3@518.79,-1027.21
GATE4: J2.05 J3.4 P2.1 | length 2007.8
  Top Layer w10: v1(250,-977.48) 250,-934.57 285.57,-899 563.83,-899 790.53,-672.3 P2.1
  Bottom Layer w10: J3.4 -718.16,-716.02 -607.18,-827 -203.37,-827 -17.64,-1012.73 214.75,-1012.73 v1(250,-977.48)
GATE5: J2.10 J3.5 P2.2 | length 2360.3
  Top Layer w10: J2.10 v1(150,-1133.5) 150,-1155.43 185.98,-1191.41 378.45,-1191.41 412.26,-1157.6 412.26,-945.34 440.6,-917 571.28,-917 739.38,-748.9 P2.2
  Bottom Layer w10: J3.5 -776.78,-697.11 -812.88,-697.11 -824.67,-708.9 -824.67,-795.74 -804.44,-815.97 -720.03,-815.97 -637,-899 -233.19,-899 -47.46,-1084.73 120.18,-1084.73 146.56,-1111.11 146.56,-1130.06 v1(150,-1133.5)
GATE6: J2.09 J3.6 P2.3 | length 1777.7
  Bottom Layer w10: J3.6 -775.22,-677.43 -731.3,-677.43 -605.72,-803 -201.91,-803 -61.13,-943.79 116.31,-943.79 v1(150,-977.48) 228.48,-899 611.67,-899 669.18,-841.49 783.32,-841.49 799.31,-825.51 P2.3
GATE_AMP: J2.21
GND: C1.2 C2.2 C7.1 C8.2 J1.01 J1.02 J1.07 J1.08 J1.11 J1.13 J1.14 J1.16 J1.19 J1.24 J1.27 J2.01 J2.02 J2.07 J2.08 J2.11 J2.12 J2.15 J2.16 J2.20 J2.23 J2.28 J4.2 U1.20 U1.21 U1.23 U1.24 U2.20 U2.21 U2.23 U2.24 U3.4 | length 1092.2
  Top Layer w10: v1(-402.99,1138) -399.55,1141.44 -399.55,1150.57 -369.12,1181 -325.57,1181 -300,1155.43 J1.27 ; v1(-127,673) -89.01,673 C7.1 ; U3.4 292.69,821.93 v1(292.69,847.4) ; J1.01 J1.02 354.52,972.96 v1(382.47,972.96)
  Bottom Layer w10: v1(50,977.48) 53.44,974.04 53.44,957.25 118.69,892 J4.2 ; v1(229.82,-569.81) 229.82,-572.26 243.98,-586.42 ; U2.24 U2.23 260.8,-630.6 239.03,-608.82 239.03,-591.37 243.98,-586.42 ; v1(270.9,-120.37) 270.9,-91.67 U1.24 U1.23 260.8,-53.24 239.03,-31.47 239.03,-14.02 248.93,-4.12 266.37,-4.12 288.15,-25.9 U1.21 U1.20 ; U2.20 U2.21 288.15,-603.25 266.37,-581.47 248.93,-581.47 243.98,-586.42 ; C2.2 523.36,-546.2 v1(555.43,-514.13) ; C1.2 524.05,44.59 v1(551.01,71.54) ; C8.2 935.23,-38.56 v2(935.23,-78.24)
  other v1: 100,-1133.5 350,-1133.5 0.44,-1130.06 -300,-1112.52 -100,-1112.52 200,-1084.73 -200,-977.48 0,-977.48 100,-977.48 200,-977.48 350,-977.48 -529,-975 -61.13,-848.42 -907.86,-770.34 570,-733.61 -974,-697.33 625.69,-675 448.23,-673.59 459.36,-608.82 -952.8,-597.91 -995.21,-489.1 -921.01,-420.74 497.35,-416.73 -937.98,-363.07 498.78,-315.21 -882.4,-282.94 453.1,-265.82 423.66,-219.16 51.76,-216.43 -31.71,-199.47 596.04,-199.47 219.34,-195.24 164.93,-179.8 371.78,-167.57 -872.35,-160 316.48,-149.87 596.04,-132.24 -913.48,-95.04 -949.89,-27.82 669.18,-25.94 -969,46.98 -1005,119 446.14,123.04 583.51,188.46 -977.13,196.73 -957.06,233.59 502.22,270.7 -937.98,302.22 451.15,327.29 -879.48,345.89 407.69,366.52 200,386.35 351.41,393.09 45.95,401.3 134.37,410.75 292.69,425.72 157.08,573.31 539.36,601.99 454.89,676.9 14.43,728.98 213.14,751.94 388.31,760.68 -325.57,796.22 -437.6,910.16 -200,977.48 0,977.48 200,977.48 -100,1112.52 50,1112.52 100,1112.52 200,1112.52
GPIO13: J2.18
HEAT_THERM_BUFF: J2.25
IDS: C3.1 C4.1 C5.1 C6.2 pad.3 R1.1 U1.43 U3.2 | length 1720.5
  Top Layer w10: v1(214.69,713.03) 216.17,714.51 285.27,714.51 U3.2 390.68,716 395.33,711.35 472.31,711.35 491.02,730.06 C4.1 ; v1(496.04,676.9) 496.04,728.98 C4.1 ; pad.3 544.17,1017.29 418.47,891.59 C3.1 432.17,823.85 432.17,796.79 491.02,737.94 C4.1 ; v1(571.77,621.89) 576.64,621.89 583.64,614.89 C5.1 646.68,573.31 684.22,535.78 688.66,535.78 702.36,522.08 C6.2
  Bottom Layer w10: U1.43 102.12,244.63 8.26,338.5 8.26,515.22 186.33,693.3 193.41,693.3 213.14,713.03 v1(214.69,713.03) ; v1(496.04,676.9) 531.23,676.9 568.5,639.63 568.5,625.16 v1(571.77,621.89)
IDS1: J3.39 P3.1 U1.12 | length 2376.1
  Top Layer w10: v1(-857.54,-125.46) -853.9,-125.46 -842.68,-114.24 141.44,-114.24 419.67,163.99 v1(477.4,163.99)
  Bottom Layer w10: P3.1 -1143.26,86.23 -931,-126.04 -896.63,-126.04 -896.06,-125.46 v1(-857.54,-125.46) -836.5,-104.43 -836.5,-48.49 -815.95,-27.94 -776.91,-27.94 J3.39 ; U1.12 404.09,164.72 405.27,164.72 415.32,154.67 463.21,154.67 472.53,163.99 v1(477.4,163.99)
IDS2: J3.40 U1.11 | length 1777
  Top Layer w10: v1(-875.02,-90.27) 130.74,-90.27 416,194.99 490.24,194.99 491.72,193.52 498.78,193.52 v1(502.22,190.07)
  Bottom Layer w10: v1(-875.02,-90.27) -854.5,-69.74 -854.5,-41.04 -820.81,-7.35 J3.40 ; U1.11 386.57,174.54 410.35,198.32 448.15,198.32 450.93,195.54 491.88,195.54 497.35,190.07 v1(502.22,190.07)
IDS3: J3.41 U1.10 | length 1784.4
  Top Layer w10: v1(-896.01,-59.27) 127.02,-59.27 408.5,222.21 480.48,222.21 481.37,223.09 489.05,223.09 v1(492.49,226.54)
  Bottom Layer w10: v1(-896.01,-59.27) -872.5,-35.75 -872.5,-33.58 -826.59,12.33 J3.41 ; U1.10@379.05,194.86 400.51,216.32 477.4,216.32 487.62,226.54 v1(492.49,226.54)
IDS4: J3.42 U1.9 | length 1764
  Top Layer w10: v1(-909.63,-25.94) 118.69,-25.94 397.33,252.7 467.13,252.7 v1(467.64,253.21)
  Bottom Layer w10: v1(-909.63,-25.94) -906.19,-22.5 -906.19,-12.2 -901.78,-7.8 -901.78,-6.52 -863.24,32.02 J3.42@-799.81,32.02 ; U1.9 391.81,235.96 446.14,235.96 463.39,253.21 v1(467.64,253.21)
IDS5: J3.43 U1.8 | length 1816.5
  Top Layer w10: v1@-932.77,5.06 112.29,5.06 377.92,270.7 432.78,270.7 448.23,286.14 v1(453.1,286.14)
  Bottom Layer w10: v1(-932.78,5.04) -927.91,5.04 -922.91,10.04 -919.59,10.04 -877.93,51.7 J3.43 ; U1.8 386.51,258.5 426.05,258.5 453.1,285.55 v1(453.1,286.14)
IDS6: J3.44 U1.7 | length 1747.6
  Top Layer w10: v1(-932.43,41.04) 113.74,41.04 371.78,299.08 416.89,299.08 v1(419.51,301.7)
  Bottom Layer w10: v1(-932.43,41.04) -902.08,71.39 J3.44 ; U1.7 398.43,298.25 416.06,298.25 v1(419.51,301.7)
IDS7: J3.45 U1.6 | length 1744.7
  Top Layer w10: v1(-944.64,74.91) 122.15,74.91 364.32,317.08 380.89,317.08 394.57,330.76 v1(398.26,330.76)
  Bottom Layer w10: v1(-944.64,74.91) -941.2,78.35 -920.57,78.35 -907.86,91.07 J3.45 ; U1.6 316.48,244.63 398.26,326.41 v1(398.26,330.76)
IDS8: J3.46 U1.5 | length 1772.4
  Top Layer w10: v1(-969.9,103.7) -967.7,105.91 127.69,105.91 364.58,342.79 364.58,343.1 372.1,350.61 v1(372.1,355.49)
  Bottom Layer w10: v1(-969.9,103.7) -967.7,105.91 -925.07,105.91 -920.23,110.76 J3.46 ; U1.5 364.58,320.08 364.58,343.1 372.1,350.61 v1(372.1,355.49)
IDS9: J3.47 U1.4 | length 1733.6
  Top Layer w10: v1(-982,150.13) -977.13,150.13 -961.7,134.7 -960.7,134.7 -958.54,132.54 -945.07,132.54 -942.97,130.44 108.59,130.44 333.58,355.43 v1(333.58,355.63)
  Bottom Layer w10: v1(-982,150.13) -977.13,150.13 -961.7,134.7 -957.06,134.7 -952.8,130.44 J3.47 ; U1.4 333.58,316.92 v1(333.58,355.63)
IDS10: J3.48 U1.3 | length 1639.3
  Top Layer w10: v1(-945.7,163.54) 100.71,163.54 301.89,364.73 v1(301.89,385.96)
  Bottom Layer w10: v1(-945.7,163.54) -940.83,163.54 -927.41,150.13 J3.48 ; U1.3 274.72,286.39 302.58,314.25 302.58,385.27 v1(301.89,385.96)
IDS11: J3.49 U1.2 | length 1584.5
  Top Layer w10: v1(-931.76,196.73) -926.89,196.73 -920.84,190.69 102.39,190.69 266.6,354.89 v1(266.6,393.09)
  Bottom Layer w10: v1(-931.76,196.73) -904.84,169.81 J3.49 ; U1.2 270.38,309.39 270.38,310.5 284.58,324.7 284.58,340.36 266.6,358.34 v1(266.6,393.09)
IDS12: J3.50 U1.1 | length 1360.6
  Top Layer w10: v1(-905.81,221.69) 89.55,221.69 v1(213.76,345.89)
  Bottom Layer w10: v1(-905.81,221.69) -873.62,189.5 J3.50 ; v1(213.76,345.89) 245.91,313.74 U1.1
IDS13: J3.51 U1.48 | length 1394.1
  Top Layer w10: v1(-925.88,262.06) -921.01,262.06 -914.09,255.14 77.03,255.14 135.03,313.14 135.03,349.34 v1(157.08,371.39)
  Bottom Layer w10: v1(-925.88,262.06) -922.44,258.61 -913.64,258.61 -913.48,258.45 -898.73,258.45 -849.46,209.18 J3.51 ; v1(157.08,371.39) 157.08,366.52 152.93,362.37 152.93,332.53 U1.48
IDS14: J3.52 U1.47 | length 1337.7
  Top Layer w10: v1(-900.64,289.45) -895.77,289.45 -882.93,276.61 73.04,276.61 117.03,320.6 117.03,371.39 v1(115.14,373.29)
  Bottom Layer w10: v1(-900.64,289.45) -900.64,285.82 -843.69,228.87 J3.52 ; v1(115.14,373.29) 117.03,371.39 117.03,340.58 U1.47
IDS15: J3.53 U1.46 | length 1270.5
  Top Layer w10: v1(-869.56,307.61) -864.69,307.61 -859.3,302.22 73.2,302.22 91.36,320.38 91.36,350.96 74.5,367.82 v1(74.5,372.69)
  Bottom Layer w10: v1(-869.56,307.61) -866.11,304.16 -866.11,292.17 -822.5,248.55 J3.53 ; v1(74.5,372.69) 74.5,367.82 98.11,344.2 98.11,331.66 U1.46
IDS16: J3.54 U1.45 | length 1126.4
  Top Layer w10: v1(-845.21,334.13) -840.34,334.13 -828.58,345.89 v1(47.7,345.89)
  Bottom Layer w10: v1(-845.21,334.13) -845.21,329.26 -838.56,322.6 -838.56,294.69 -812.88,269.02 -776.78,269.02 J3.54 ; v1(47.7,345.89) 48.98,345.89 68.84,326.03 75.91,326.03 U1.45
IDS17: J3.55 U1.25 | length 1148.5
  Bottom Layer w10: J3.55 -563.19,287.92 -143.03,-132.24 107.14,-132.24 U1.25
IDS18: J3.56 U1.26 | length 1133.6
  Bottom Layer w10: J3.56 -545.32,307.61 -123.48,-114.24 97.3,-114.24 U1.26
IDS19: J3.57 U1.27 | length 1118.7
  Bottom Layer w10: J3.57 -535.09,327.29 -111.56,-96.24 87.46,-96.24 U1.27
IDS20: J3.58 U1.28 | length 1103.8
  Bottom Layer w10: J3.58 -516.83,346.98 -91.62,-78.24 77.62,-78.24 U1.28
IDS21: J3.59 U1.29 | length 1088.9
  Bottom Layer w10: J3.59 -506.87,366.66 -79.97,-60.24 67.78,-60.24 U1.29
IDS22: J3.60 U1.30 | length 1073.9
  Bottom Layer w10: J3.60 -501.1,386.35 -72.51,-42.24 57.94,-42.24 U1.30
IDS23: J3.61 U1.31 | length 1059
  Bottom Layer w10: J3.61 -495.33,406.03 -65.06,-24.24 48.1,-24.24 U1.31
IDS24: J3.62 U1.32 | length 1044.1
  Bottom Layer w10: J3.62 -489.55,425.72 -57.6,-6.24 38.26,-6.24 U1.32
IDS25: J3.63 U1.33 | length 1029.2
  Bottom Layer w10: J3.63 -483.78,445.4 -50.15,11.76 27.93,11.76 59.87,43.7 U1.33
IDS26: J3.64 U1.34 | length 1014.3
  Bottom Layer w10: J3.64 -478.01,465.09 -42.69,29.76 18.1,29.76 45.95,57.62 U1.34
IDS27: J3.65 U1.35 | length 999.4
  Bottom Layer w10: J3.65 -459.36,484.77 -22.35,47.76 8.26,47.76 32.03,71.54 U1.35
IDS28: J3.66 U1.36 | length 989.1
  Bottom Layer w10: J3.66 -378.83,504.46 18.6,107.02 18.6,106.74 28.65,96.69 28.65,95.51 U1.36
IDS29: J3.67 U1.37 | length 945.2
  Bottom Layer w10: J3.67 -344.91,524.14 U1.37
IDS30: J3.68 U1.38 | length 961.5
  Bottom Layer w10: J3.68 -336.76,543.83 U1.38
IDS31: J3.69 U1.39 | length 977.8
  Bottom Layer w10: J3.69 -328.61,563.51 U1.39
IDS32: J3.70 P3.2 U1.40 | length 1361
  Bottom Layer w10: P3.2 -989.2,482 -888,583.2 J3.70 -320.45,583.2 U1.40
LOW_BATT: J2.29
MISO: J1.22 R2.2 | length 229.1
  Top Layer w10: J1.22 -150,818.35 -107.5,775.84 R2.2
MOSI: J1.30 J4.5 | length 635.5
  Top Layer w10: v1(-402.99,935.5) -399.55,938.94 -399.55,959.2 -381.26,977.48 J1.30
  Bottom Layer w10: v1(-402.99,935.5) -402.99,791.8 -335.19,724 -206.82,724 -117.53,813.29 J4.5
NetJ4_4: J4.4 R2.1 | length 164.4
  Top Layer w10: R2.1 v1(-0.4,766)
  Bottom Layer w10: J4.4 -38.79,804.39 v1(-0.4,766)
SCAN: J2.27
SCK: J1.20 J4.3 | length 203.7
  Bottom Layer w10: v1(-100,977.48) -100,972.61 -92.27,964.88 -92.27,954.99 -80.39,943.11 -11.16,943.11 39.95,892 J4.3
SOURCE_SEL0: J1.26 U1.15 | length 2237.6
  Top Layer w10: J1.26 -250,890.17 -255.86,884.31 -349.1,884.31 -402.99,830.42 -402.99,751.94 -135.48,484.43 433.74,484.43 656.53,261.65 656.53,30.72 671.02,16.23 v1(671.02,15.86)
  Bottom Layer w10: U1.15 412.85,16.93 412.85,6.91 473.49,-53.73 540.08,-53.73 609.68,15.86 v1(671.02,15.86)
SOURCE_SEL1: J1.25 U1.16 | length 2598.5
  Top Layer w10: J1.25 -259.57,1122.09 -259.57,1172.57 -290,1203 -383.57,1203 -472.24,1114.32 -472.24,795.74 -141.59,465.09 427.63,465.09 629.42,263.3 v1(629.42,-25.9)
  Bottom Layer w10: U1.16 394.85,7.09 394.85,-0.55 466.11,-71.8 583.51,-71.8 v1(629.42,-25.9)
SOURCE_SEL2: J2.17 U1.17 | length 1751.7
  Top Layer w10: J2.17 -40.43,-967.91 -40.43,-916.41 -0.12,-876.1 0.44,-876.1 18.6,-857.94 18.6,-857.38 41.9,-834.08 391.45,-834.08 679.54,-545.99 679.54,-142.87 v1(632.91,-96.24)
  Bottom Layer w10: U1.17 376.85,-2.75 376.85,-8 465.08,-96.24 v1(632.91,-96.24)
SOURCE_SEL3: J2.30 U1.18 | length 2227.1
  Top Layer w10: J2.30 -350,-1084 -359.57,-1074.43 -373.71,-1074.43 -424.38,-1023.76 -424.38,-917.36 -321.12,-814.1 385.97,-814.1 656.53,-543.54 656.53,-206.21 v1(614.01,-163.7)
  Bottom Layer w10: U1.18 330.4,15.37 358.85,-13.08 358.85,-15.46 507.09,-163.7 v1(614.01,-163.7)
SOURCE_SEL4: J2.26 U1.19 | length 2409.5
  Top Layer w10: J2.26 -250,-1155.43 -277.57,-1183 -369.95,-1183 -442.38,-1110.57 -442.38,-909.91 -328.57,-796.1 378.51,-796.1 637.15,-537.46 637.15,-274.75 v1(601.3,-238.89)
  Bottom Layer w10: U1.19 316.48,1.45 556.83,-238.89 v1(601.3,-238.89)
VDS1: J3.7 P4.1 U2.12 | length 2105.7
  Top Layer w10: v1(-873,-755.39) -823.61,-706 205.19,-706 v1(465.19,-446)
  Bottom Layer w10: P4.1 -1016,-598.2 -1016,-713.1 -927.75,-801.34 -895.01,-801.34 -876.44,-782.77 -876.44,-758.83 v1(-873,-755.39) -872.35,-754.74 -872.35,-717.21 -812.88,-657.74 -776.78,-657.74 J3.7 J3.7@-775.22,-657.74 ; U2.12 416.01,-400.71 417.2,-400.71 462.49,-446 v1(465.19,-446)
VDS2: J3.8 U2.11 | length 1839.3
  Top Layer w10: v1(-903.35,-725.56) -902.18,-724.39 -867.46,-724.39 -831.07,-688 172.03,-688 v1(498.75,-361.28)
  Bottom Layer w10: v1(-903.35,-725.56) -903.35,-722.76 -818.65,-638.06 -776.78,-638.06 J3.8 ; U2.11@392.2,-395.59 393.79,-395.59 414,-375.37 479.81,-375.37 493.9,-361.28 v1(498.75,-361.28)
VDS3: J3.9 U2.10 | length 1858.2
  Top Layer w10: v1(-937.98,-694.55) -863.08,-694.55 -838.53,-670 85.78,-670 398.76,-357.03 452.11,-357.03 464.76,-344.37 v1(466.97,-344.37)
  Bottom Layer w10: v1(-937.98,-694.55) -905.89,-694.55 -828.93,-617.59 J3.9 J3.9@-775.22,-618.37 ; U2.10 405.73,-355.32 451.15,-355.32 462.1,-344.37 v1(466.97,-344.37)
VDS4: J3.10 U2.9 | length 1934
  Top Layer w10: v1(-969,-661.68) -967.13,-663.55 -857.54,-663.55 -845.98,-652 76.54,-652 395.33,-333.21 434.29,-333.21 v1(462.13,-305.37)
  Bottom Layer w10: v1(-969,-661.68) -967.13,-663.55 -914.31,-663.55 -849.44,-598.68 -776.78,-598.68 J3.10 ; U2.9 400.31,-332.89 434.6,-332.89 v1(462.13,-305.37)
VDS5: J3.11 U2.8 | length 1799.6
  Top Layer w10: v1(-937.98,-632.55) 67.7,-632.55 385.04,-315.21 405.85,-315.21 v1(426.83,-294.24)
  Bottom Layer w10: v1(-937.98,-632.55) -908.76,-632.55 -854.43,-578.22 J3.11 ; U2.8 407.69,-297.68 423.38,-297.68 v1(426.83,-294.24)
VDS6: J3.12 U2.7 | length 1752.7
  Top Layer w10: v1(-914.5,-594.45) -911.05,-597.89 -900.43,-597.89 -899.64,-598.68 76.11,-598.68 v1(416.89,-257.91)
  Bottom Layer w10: v1(-914.5,-594.45) -911.05,-591.01 -892.67,-591.01 -860.69,-559.02 -776.49,-559.02 J3.12 ; U2.7 330.4,-346.64 416.89,-260.15 v1(416.89,-257.91)
VDS7: J3.13 U2.6 | length 1736.9
  Top Layer w10: v1(-898.12,-552.62) -896.24,-552.62 -883.26,-565.59 67.02,-565.59 388.31,-244.3 v1(388.31,-211.52)
  Bottom Layer w10: v1(-898.12,-552.62) -893.25,-552.62 -879.48,-538.85 J3.13 ; U2.6 385.89,-263.8 385.89,-242.39 387.76,-240.52 387.76,-212.07 v1(388.31,-211.52)
VDS8: J3.14 U2.5 | length 1799.2
  Top Layer w10: v1(-982,-527) -949.89,-527 -942.06,-519.17 87.98,-519.17 352.59,-254.56 352.59,-230.92 v1(356.04,-227.48)
  Bottom Layer w10: v1(-982,-527) -949.89,-527 -942.06,-519.17 J3.14 ; U2.5 356.04,-265.82 v1(356.04,-227.48)
VDS9: J3.15 U2.4 | length 1771.1
  Top Layer w10: v1(-955.83,-489.1) -950.96,-489.1 -938.89,-501.17 80.53,-501.17 325.04,-256.66 325.04,-213.61 338.54,-200.11 v1(338.54,-195.24)
  Bottom Layer w10: v1(-955.83,-489.1) -952.39,-492.54 -946.6,-492.54 -937.98,-501.17 -851.9,-501.17 -849.44,-498.7 -776.78,-498.7 J3.15 ; U2.4 322.22,-271.8 322.22,-216.43 338.54,-200.11 v1(338.54,-195.24)
VDS10: J3.16 U2.3 | length 1659.9
  Top Layer w10: v1(-925.14,-470.17) -923.26,-470.17 -910.26,-483.17 51.76,-483.17 300,-234.92 v1(300,-184.52)
  Bottom Layer w10: v1(-925.14,-470.17) -923.26,-470.17 -910.26,-483.17 -859.36,-483.17 -855.21,-479.02 -776.78,-479.02 J3.16 ; U2.3 302.58,-263.59 302.58,-187.1 v1(300,-184.52)
VDS11: J3.17 U2.2 | length 1508.5
  Top Layer w10: v1(-893.96,-452.17) -890.52,-455.61 -883.25,-455.61 -882.4,-456.46 51.99,-456.46 269,-239.46 269,-216.92 264.25,-212.17 264.25,-207.16 v1(260.8,-203.71)
  Bottom Layer w10: v1(-893.96,-452.17) -893.09,-452.17 -885.15,-460.11 J3.17 ; U2.2 260.8,-277.04 284.58,-253.27 284.58,-228.02 260.8,-204.24 v1(260.8,-203.71)
VDS12: J3.18 U2.1 | length 1303.1
  Top Layer w10: v1(-869.56,-425.46) 39.15,-425.46 v1(224.38,-240.24)
  Bottom Layer w10: v1(-869.56,-425.46) -864.69,-425.46 -849.72,-440.43 J3.18 ; v1(224.38,-240.24) 246.88,-262.75 U2.1
VDS13: J3.19 U2.48 | length 1371
  Top Layer w10: v1(-903.35,-387.04) -899.91,-390.48 -855.74,-390.48 -847.16,-399.07 22.9,-399.07 147.96,-274.01 147.96,-257.91 v1(186.71,-219.16)
  Bottom Layer w10: v1(-903.35,-387.04) -899.91,-390.48 -860.69,-390.48 -830.44,-420.74 J3.19 ; U2.48 186.71,-248.63 v1(186.71,-219.16)
VDS14: J3.20 U2.47 | length 1393.3
  Top Layer w10: v1(-899.43,-347.12) -895.82,-347.12 -870.45,-372.48 -848.29,-372.48 -839.7,-381.07 15.44,-381.07 129.96,-266.55 v1(129.96,-199.47)
  Bottom Layer w10: v1(-899.43,-347.12) -874.07,-372.48 -853.24,-372.48 -824.67,-401.06 J3.20 ; v1(129.96,-199.47) 129.96,-249.69 U2.47
VDS15: J3.21 U2.46 | length 1296.5
  Top Layer w10: v1(-873,-322.32) -832.24,-363.07 7.99,-363.07 102.12,-268.94 102.12,-238.89 88.2,-224.97 v1(88.2,-224.03)
  Bottom Layer w10: v1(-873,-322.32) -869.56,-325.76 -869.56,-330.71 -818.9,-381.37 J3.21 ; v1(88.2,-224.03) 91.65,-227.48 91.65,-239.22 U2.46
VDS16: J3.22 U2.45 | length 1119.7
  Top Layer w10: v1(-843.21,-302.1) -799.03,-257.91 v1(60.36,-257.91)
  Bottom Layer w10: v1(-843.21,-302.1) -842,-303.31 -842,-331.79 -812.88,-360.91 -776.78,-360.91 J3.22 ; v1(60.36,-257.91) 63.81,-261.35 85.94,-261.35 U2.45
VDS17: J3.23 U2.25 | length 1126.7
  Bottom Layer w10: J3.23 -728,-342 -360.41,-709.59 107.14,-709.59 U2.25
VDS18: J3.24 U2.26 | length 1111.8
  Bottom Layer w10: J3.24 -695.28,-322.32 -326.01,-691.59 97.3,-691.59 U2.26
VDS19: J3.25 U2.27 | length 1096.9
  Bottom Layer w10: J3.25 -666.01,-302.63 -295.05,-673.59 87.46,-673.59 U2.27
VDS20: J3.26 U2.28 | length 1075.5
  Bottom Layer w10: J3.26 -631.3,-282.94 -258.66,-655.59 77.62,-655.59 124.6,-608.61 U2.28@125.71,-608.61
VDS21: J3.27 U2.29 | length 1067.1
  Bottom Layer w10: J3.27 -608.89,-263.26 -234.56,-637.59 67.78,-637.59 U2.29
VDS22: J3.28 U2.30 | length 1052.2
  Bottom Layer w10: J3.28 -590.55,-243.57 -214.54,-619.59 57.94,-619.59 U2.30
VDS23: J3.29 U2.31 | length 1038.2
  Bottom Layer w10: J3.29@-776,-224.67 -774.44,-223.11 -572.09,-223.11 -193.61,-601.59 48.1,-601.59 U2.31
VDS24: J3.30 U2.32 | length 1022.3
  Bottom Layer w10: J3.30 -547.73,-204.2 -168.34,-583.59 38.26,-583.59 U2.32
VDS25: J3.31 U2.33 | length 1007.4
  Bottom Layer w10: J3.31 -530.31,-184.52 -149.24,-565.59 27.93,-565.59 59.87,-533.65 U2.33
VDS26: J3.32 U2.34 | length 992.5
  Bottom Layer w10: J3.32 -501.33,-164.83 -118.57,-547.59 18.1,-547.59 45.95,-519.73 U2.34
VDS27: J3.33 U2.35 | length 977.6
  Bottom Layer w10: J3.33 -480.31,-145.15 -95.87,-529.59 8.26,-529.59 32.03,-505.81 U2.35
VDS28: J3.34 U2.36 | length 958.5
  Bottom Layer w10: J3.34 -378.33,-125.46 2.76,-506.56 3.94,-506.56 U2.36
VDS29: J3.35 U2.37 | length 923.4
  Bottom Layer w10: J3.35 -292.34,-105.78 U2.37
VDS30: J3.36 U2.38 | length 939.7
  Bottom Layer w10: J3.36 -284.19,-86.09 U2.38
VDS31: J3.37 U2.39 | length 956
  Bottom Layer w10: J3.37 -276.04,-66.41 U2.39
VDS32: J3.38 P4.2 U2.40 | length 1544.5
  Bottom Layer w10: P4.2 -1092.79,-456.62 -1092.79,-425.9 -818.5,-151.61 -818.5,-111.88 -818.5,-55.95 -810.18,-47.63 -776.91,-47.63 J3.38 -267.88,-46.72 U2.40
VDS_BUFF: J1.09 U2.43 U3.6 U3.7 | length 2750.7
  Top Layer w10: v1(4.26,-219.16) 84.42,-139 175.8,-139 388.53,73.73 444.34,73.73 546.03,175.41 546.03,212.86 v1(549.47,216.3) ; J1.09 150,1155.43 197.57,1203 358.09,1203 413.47,1147.61 413.47,928.47 391.41,906.41 253.76,906.41 194.06,846.71 194.06,828.33 131.73,766 U3.6 U3.7 131.89,716 163.04,684.86 v1(163.04,614.89)
  Bottom Layer w10: v1(4.26,-219.16) 4.26,-273.53 26.53,-295.8 64.71,-295.8 U2.43 ; v1(163.04,614.89) 276.48,501.45 467.64,501.45 551.01,418.08 551.01,217.84 v1(549.47,216.3)
VDS_RAW: J1.10 U3.5 | length 199.5
  Top Layer w10: U3.5 130.69,816 150,835.31 J1.10
VMEAS: J1.12 R1.2 S1.8 U3.1 | length 1036.6
  Top Layer w10: v1(266.6,875.41) 173.22,782.03 173.22,710.66 217.87,666 U3.1 292.69,660.07 344.46,660.07 354.21,650.32 395.33,650.32 402.22,643.43 549.47,643.43 614.01,707.97 629.42,707.97 S1.8
  Bottom Layer w10: v1(100,977.48) 134.37,943.11 232.67,943.11 263.16,912.63 263.16,878.86 v1(266.6,875.41)
pads on no net: J3.71 J3.72 J3.73 J3.74 J3.75 J3.76 J3.77 J3.78 J3.79 J3.80 J3.81 J3.82 J3.83 J3.84 J4.7 J4.8 S1.1 S1.2 S1.3 S1.4 S1.5 U1.41 U1.42 U1.44 U2.41 U2.42 U2.44

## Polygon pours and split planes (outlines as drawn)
GND on Layer 1 (split plane): 265 vertices, not listed, extent -1279.99,-1279.99 1279.99,1279.99
GND on Layer 2 (split plane): 265 vertices, not listed, extent -1279.99,-1279.99 1279.99,1279.99

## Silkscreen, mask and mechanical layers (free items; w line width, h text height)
Top Overlay:
  lines w10: 837.93,500.22 871.08,500.22 871.08,465.09 ; 866.91,494.52 807.06,434.66 807.06,249.06 898.92,157.19 898.92,154.67
  text "IDS" at 466.15,1020.33 h30
  text "32" at -1078.79,563.38 h30
  text "IDS" at -1061,396 h30
  text "1" at -1174.76,294.92 h30
  text "POLE FREQ" at 922.59,130.44 h30
  text "500Hz" at 969.92,64.72 h30
  text "Breathalyzer- Multiplexer" at -624,63.99 h60
  text "5kHz" at 969.92,11.02 h30
  text "50kHz" at 969.92,-44.14 h30
  text "500kHz" at 969.92,-98 h30
  text "Neel Mondal         Palacios Group, MIT   April 2023" at -626.04,-195.69 h40
  text "32" at -1153.87,-392.07 h30
  text "VDS" at -1035.64,-451.39 h30
  text "1" at -1024,-650.74 h30
  text "4" at 1007,-741.9 h30
  text "GATES" at 590.48,-818.51 h30
  text "5" at 949.74,-818.51 h30
  text "6" at 872,-896 h30
  text "1" at 745.02,-1016.15 h30
  text "2" at 653.92,-1070.44 h30
  text "3" at 546.36,-1123.06 h30
Board:
  circle w5: c0,0 r1300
